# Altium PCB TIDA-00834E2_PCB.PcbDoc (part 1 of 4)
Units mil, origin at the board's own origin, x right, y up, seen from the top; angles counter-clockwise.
Board outline 7480.31 x 4133.86 mil, 4 copper layers (Top Layer, GND, PWR, Bottom Layer), stack 61.912 mil thick; 550 components, 248 nets, 1167 pads, 312 vias.
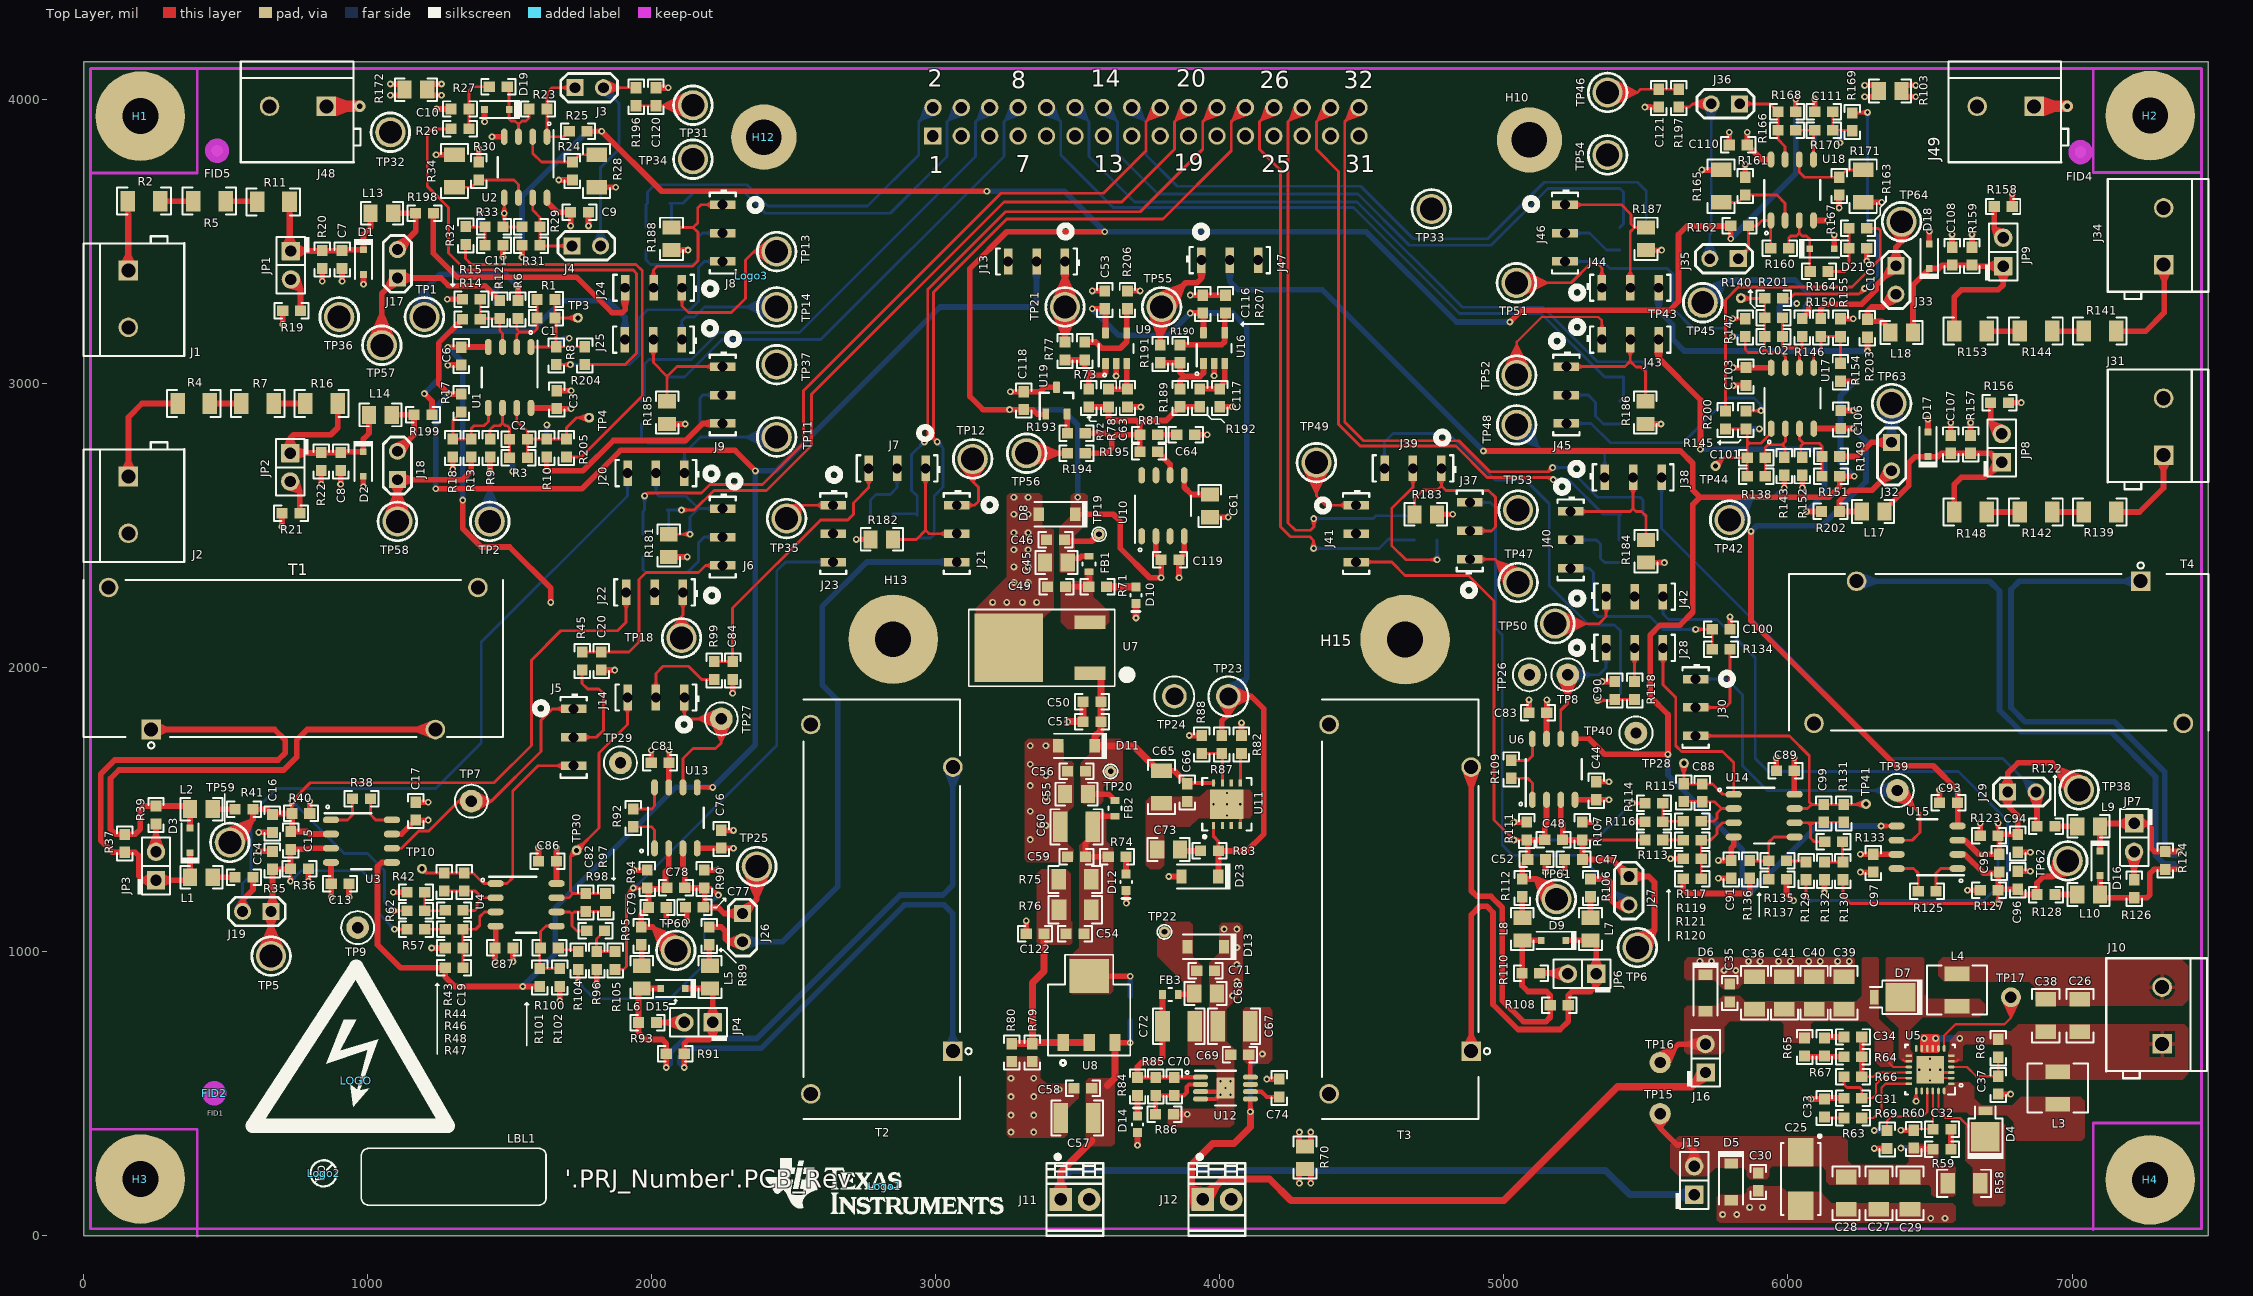
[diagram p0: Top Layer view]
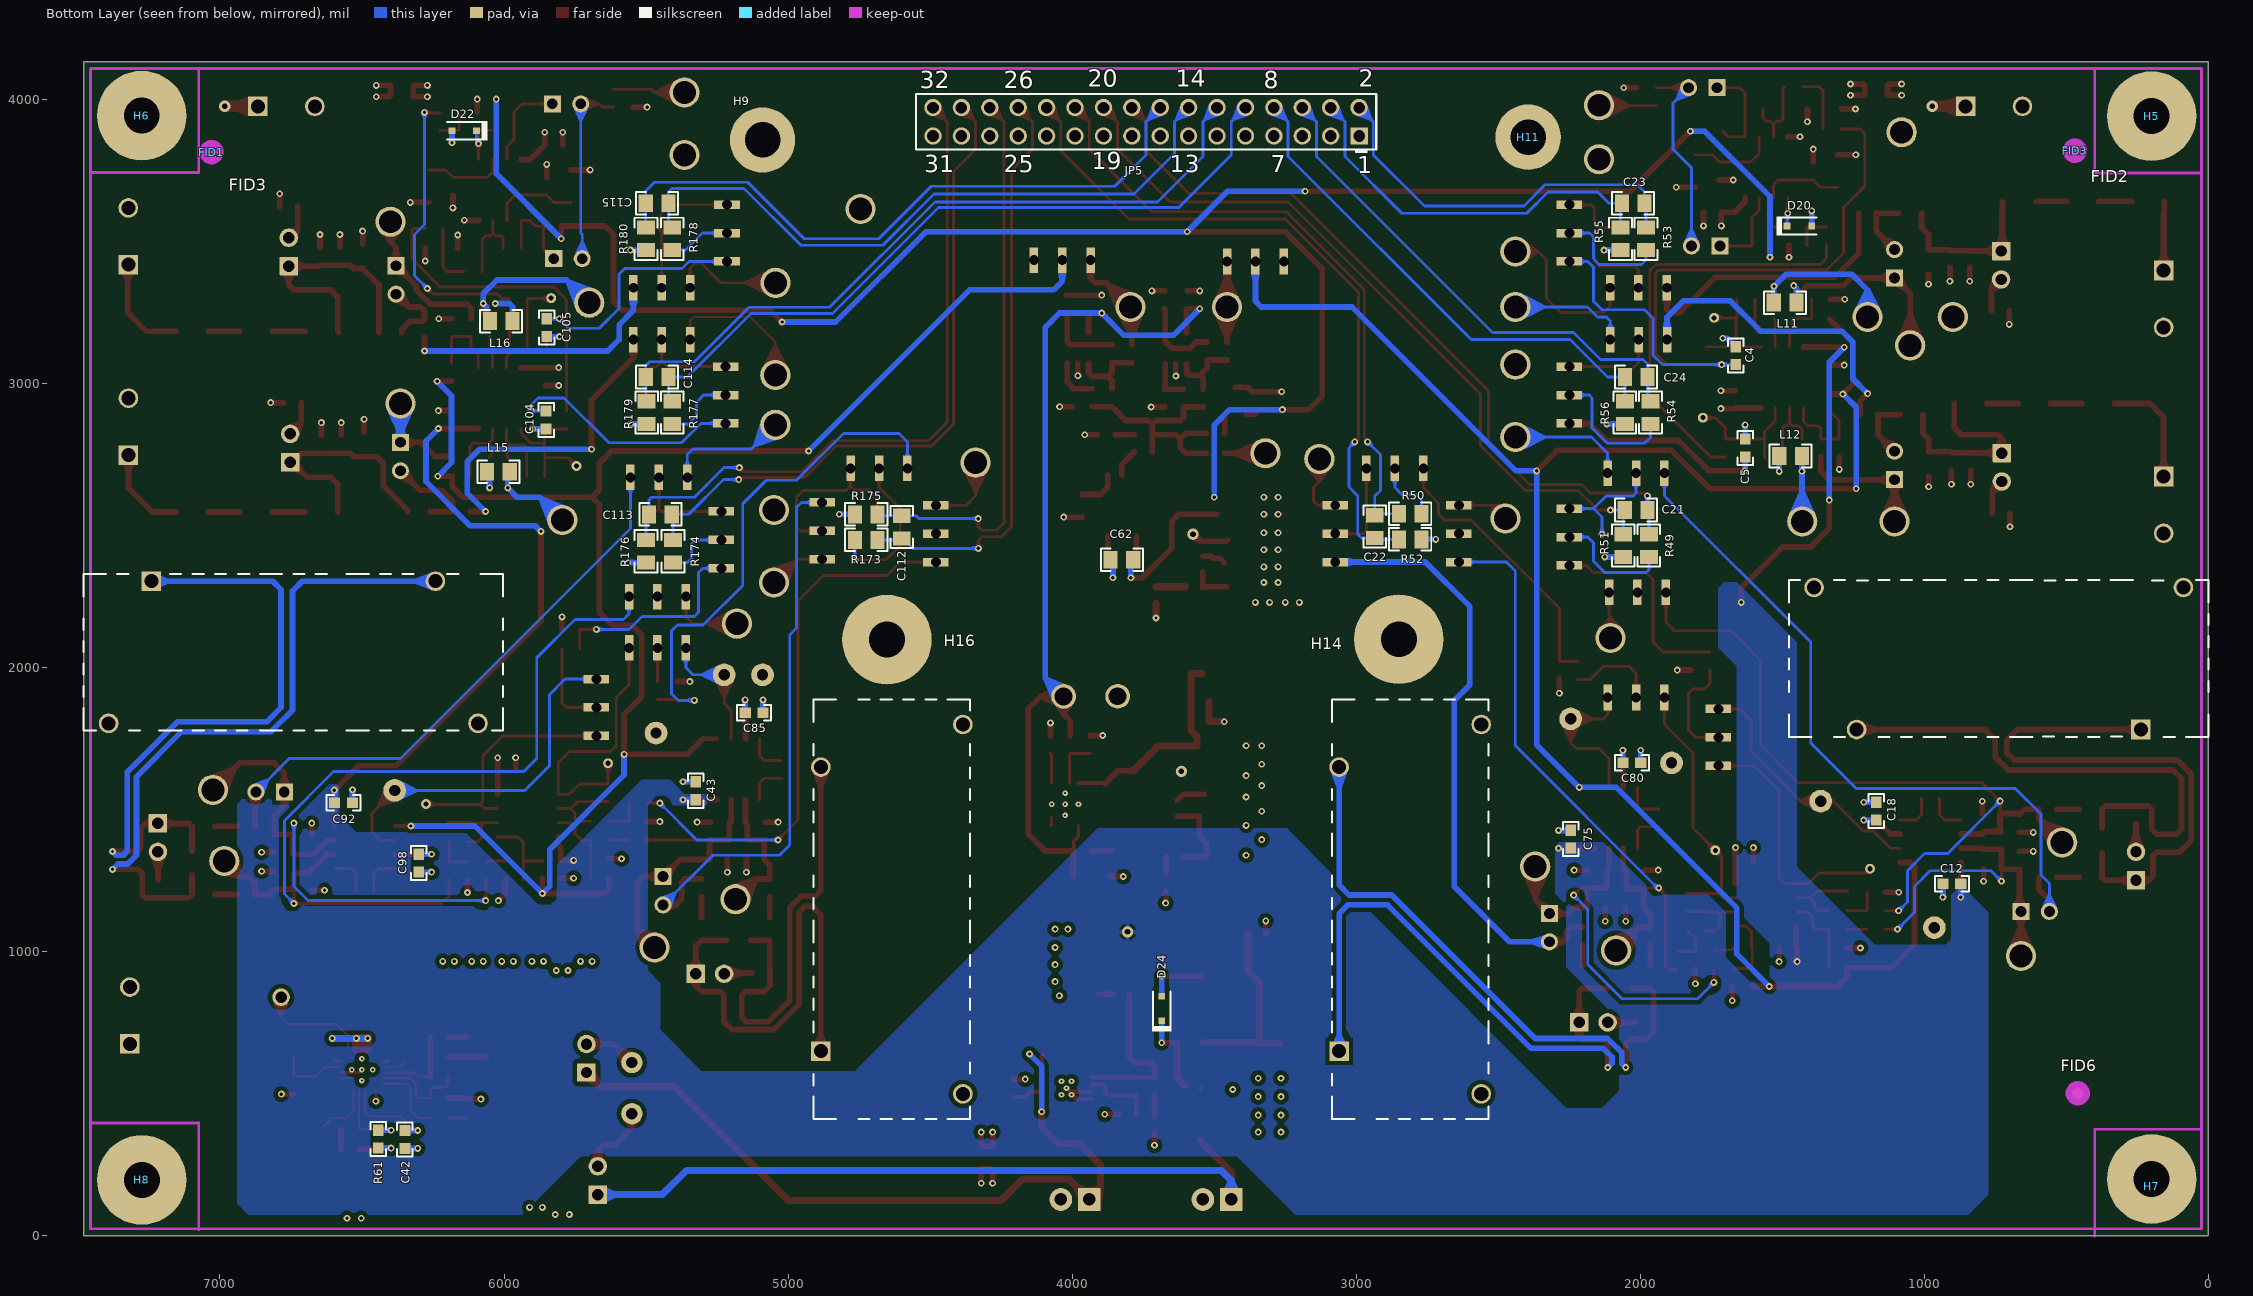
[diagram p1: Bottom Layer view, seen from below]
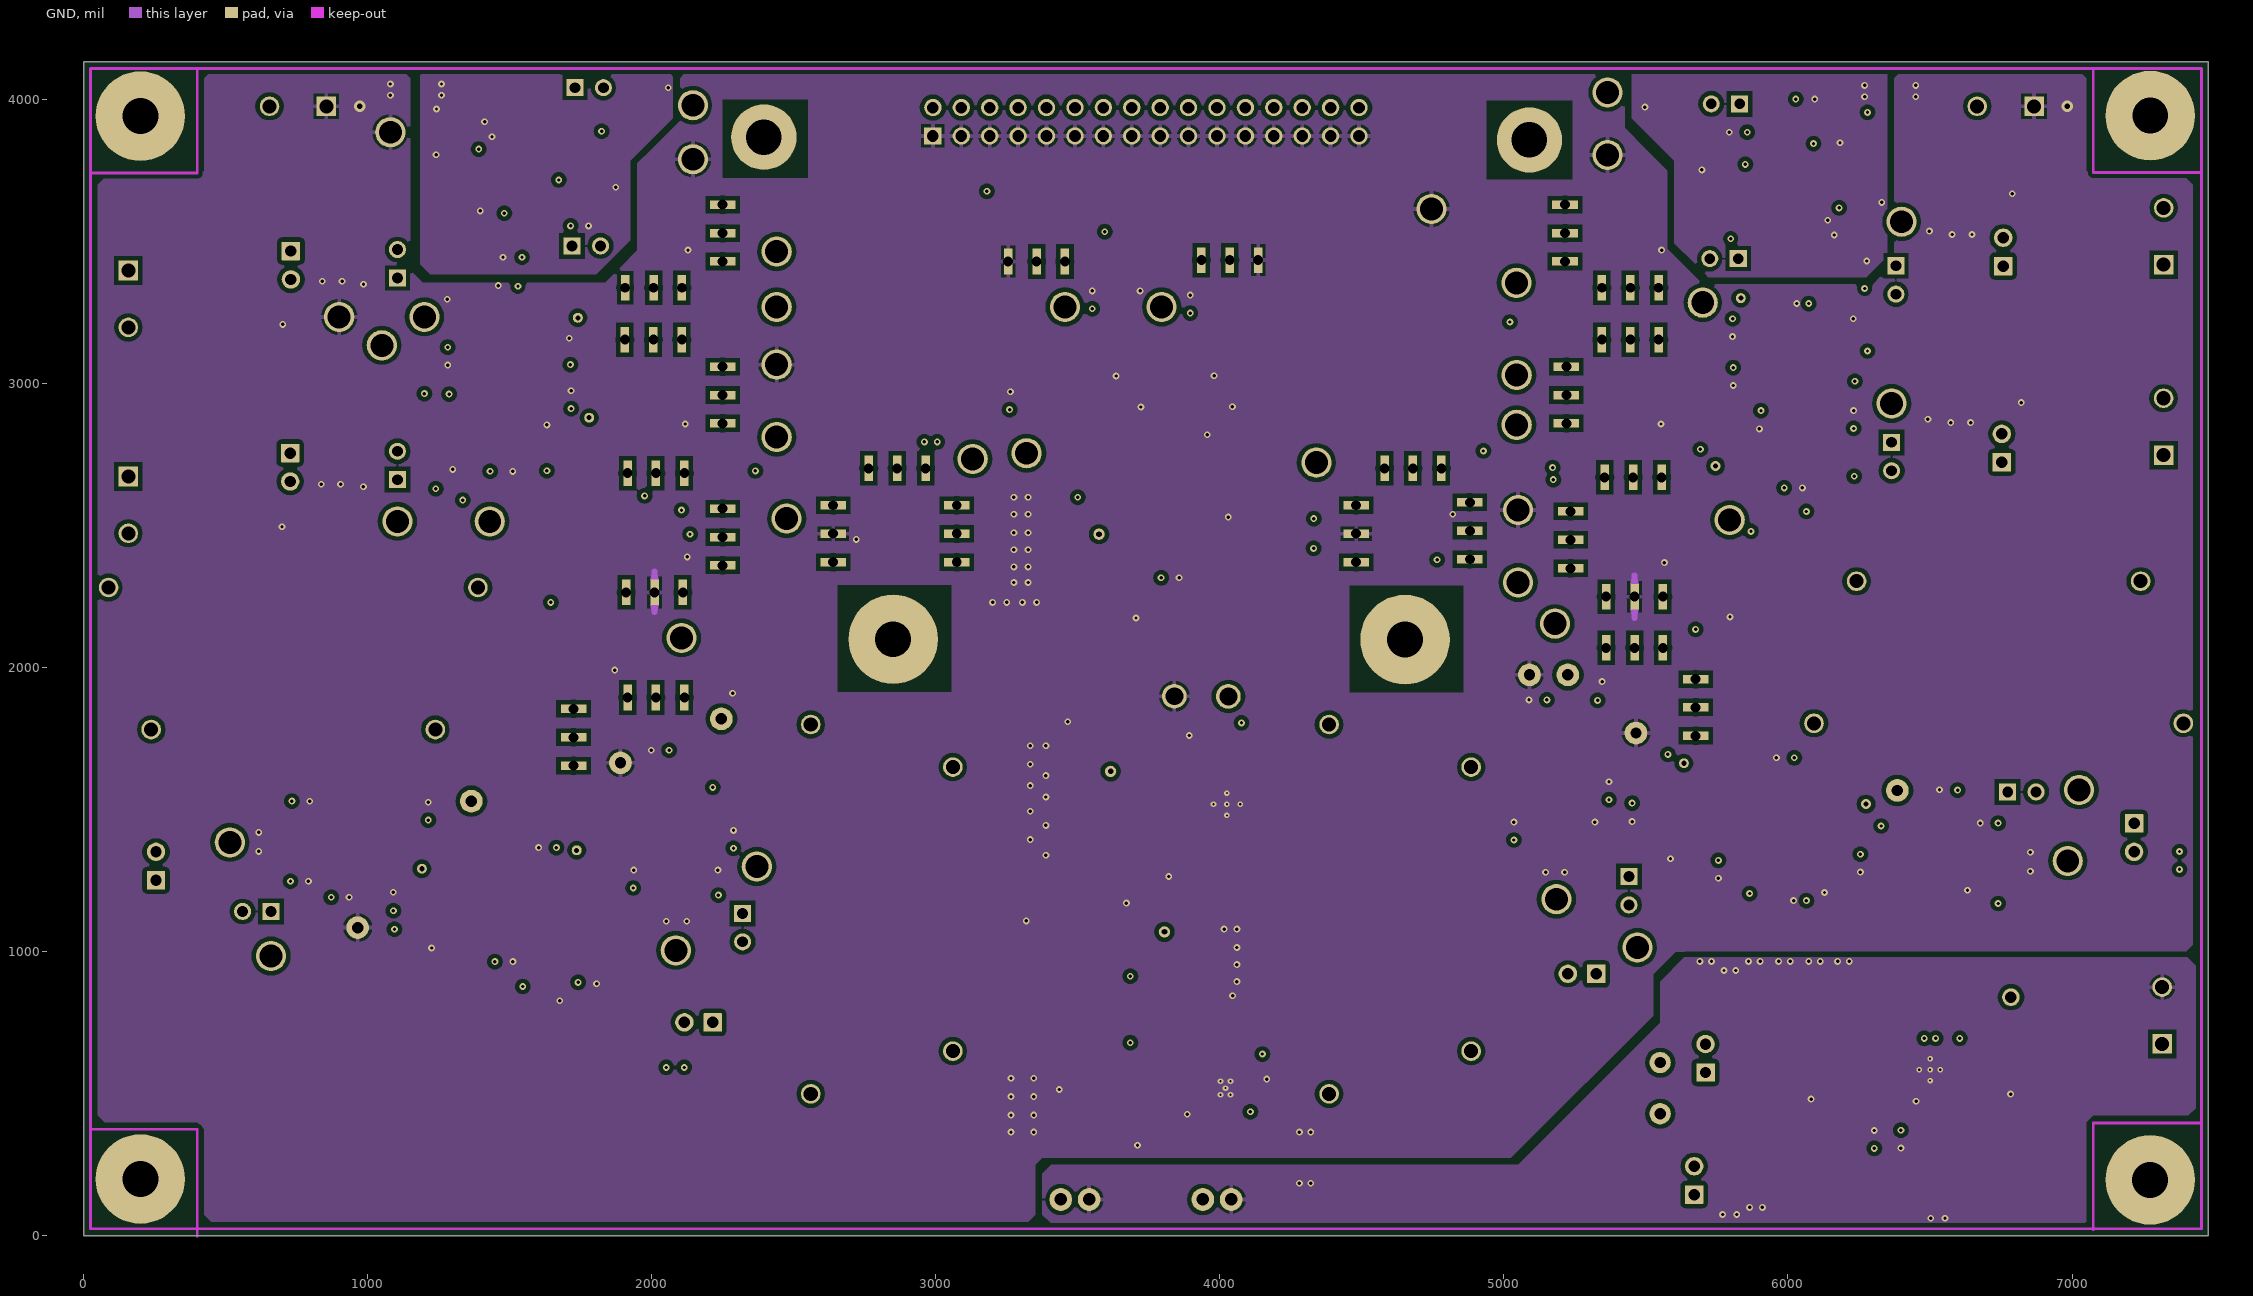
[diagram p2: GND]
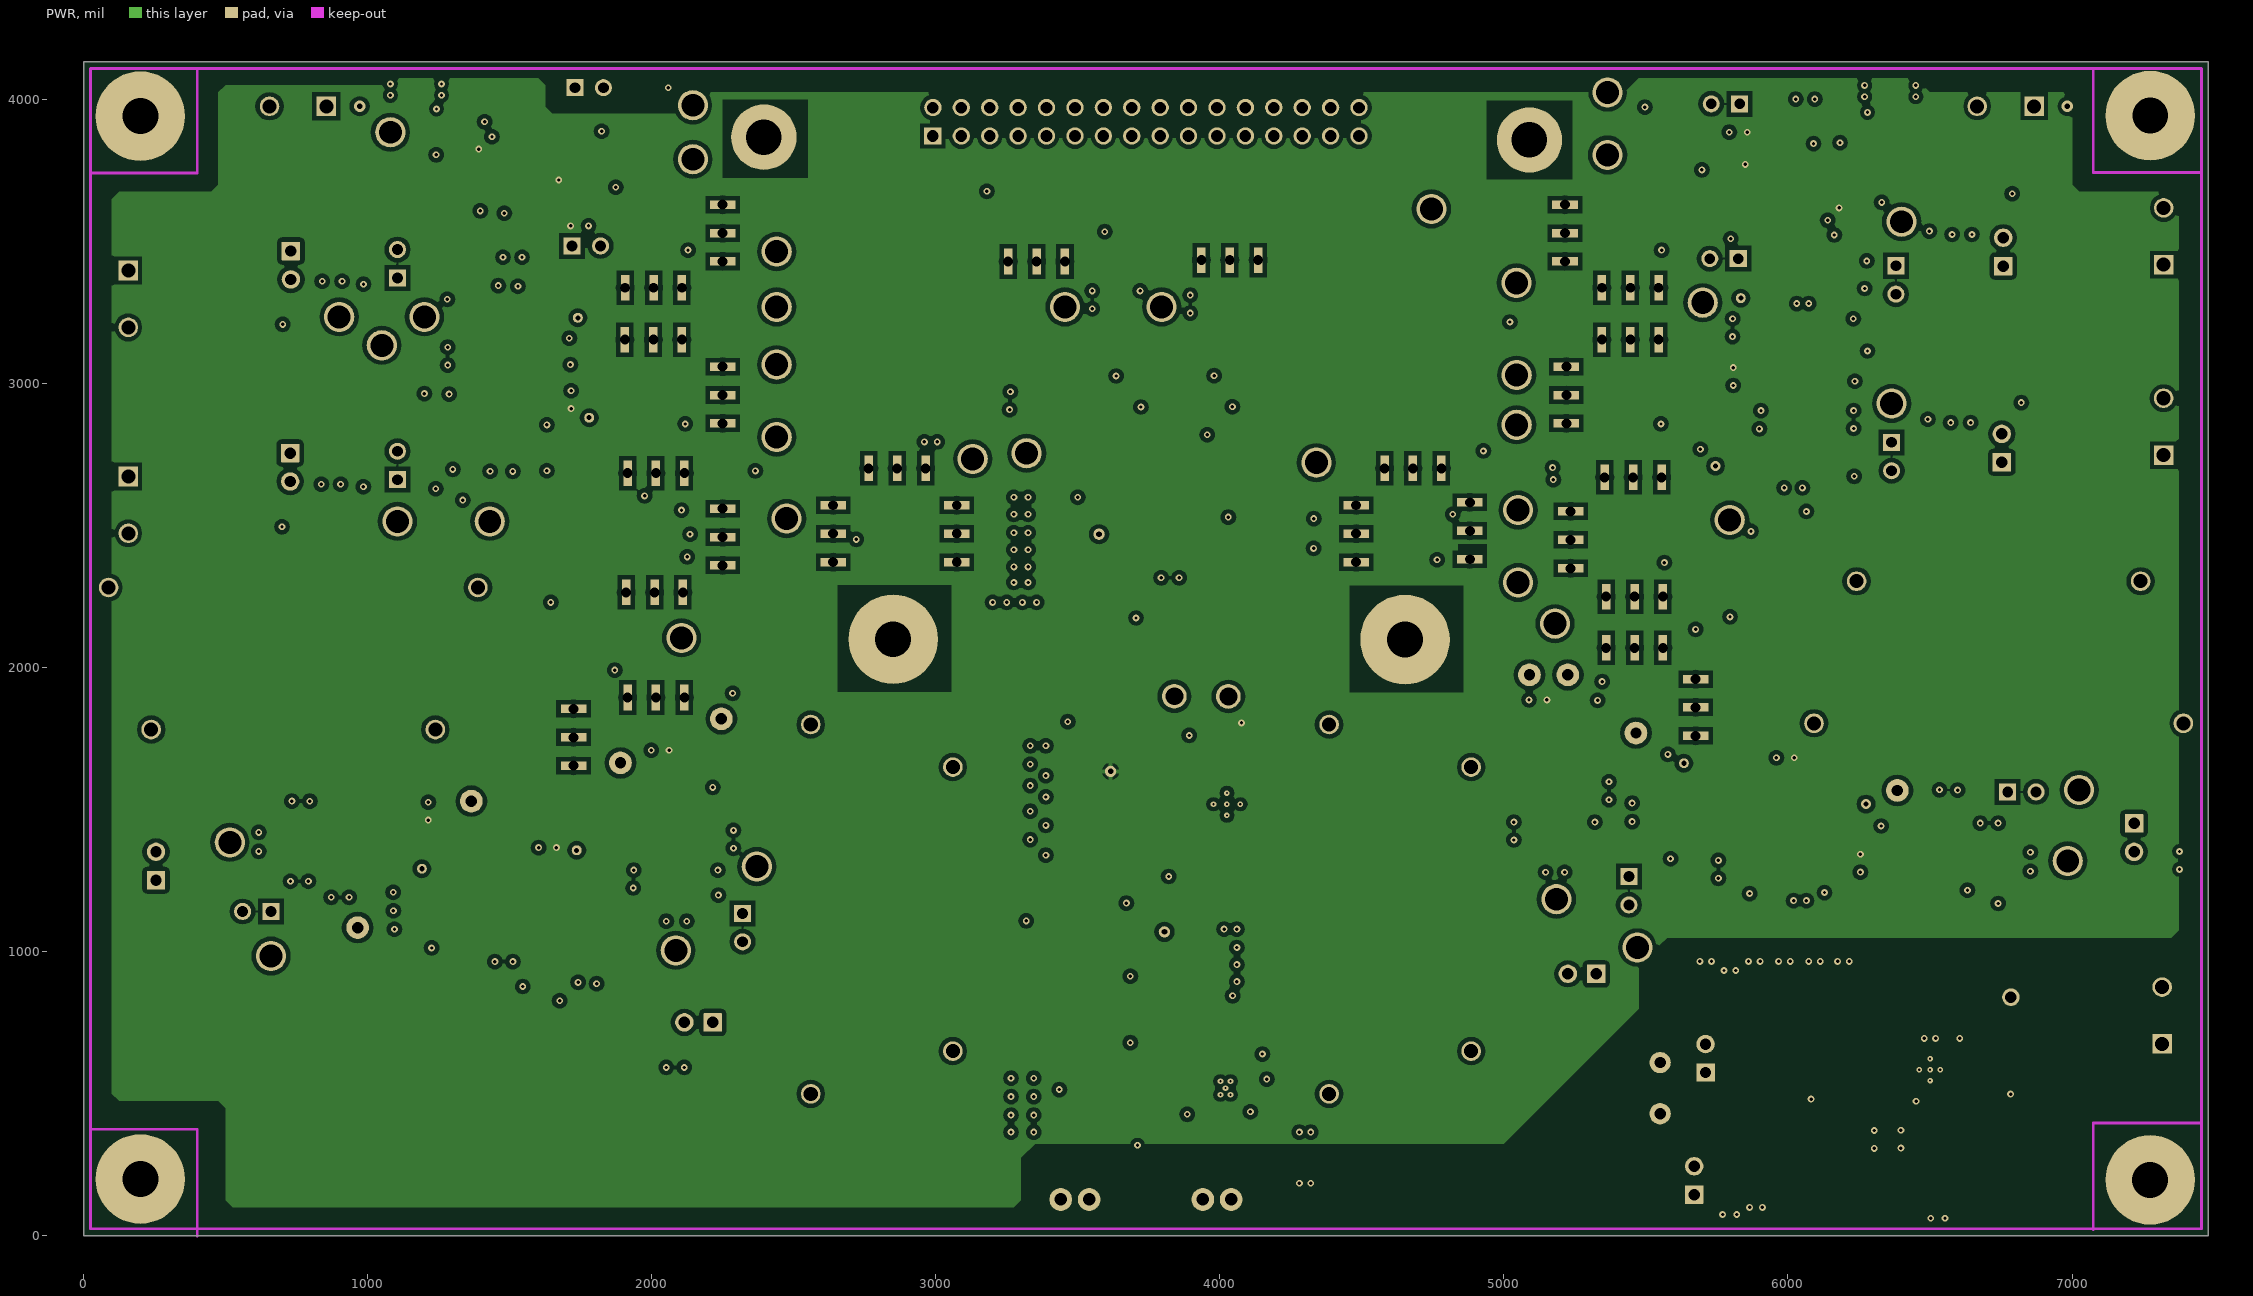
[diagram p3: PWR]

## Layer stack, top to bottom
Top Solder: solder mask 0.4, Solder Resist, Dk 4.3
Top Layer: signal copper 1.378
Dielectric1: prepreg 6.7, FR-4 High Tg, Dk 4.3
GND: signal copper 1.378
Dielectric 2: core 43, FR-4 High Tg, Dk 4.3
PWR: signal copper 1.378
Dielectric 3: prepreg 6.7, FR-4 High Tg, Dk 4.3
Bottom Layer: signal copper 1.378
Bottom Solder: solder mask 0.4, Solder Resist, Dk 4.3

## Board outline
0,0 0,4133.86 7480.31,4133.86 7480.31,0

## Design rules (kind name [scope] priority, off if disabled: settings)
AcuteAngle [All] p1: minimum=4.50000000000000E+0001 checktracksonly=FALSE
AssemblyTestPointUsage [All] p1: valid=2
Clearance Clearance_Keepouts [((IsTrack Or IsArc) And Not InPoly) And IsFree and IsKeepOut vs ((IsTrack Or IsArc) And Not InPoly) And IsFree and IsKeepOut] p1: gap=0
Clearance Clearance_Poly [InPolygon] p2: gap=25 except(8: SMDPad-Poly; 15: Track-Poly THPad-Poly Via-Poly; 20: Poly-Poly)
Clearance [All] p3: gap=7.87
ComponentClearance ComponentClearance_MountingHoles_FiducialMarks [InComponentClass('Mounting Holes') vs InComponentClass('FiducialMark')] p1: gap=50 collisioncheckmode=3 verticalgap=10 showdistances=FALSE
ComponentClearance ComponentClearance_Shunt [InComponentClass('Header') vs InComponentClass('Shunt')] p2: gap=0 collisioncheckmode=3 verticalgap=0 showdistances=FALSE
ComponentClearance ComponentClearance_Logo [InComponentClass('Logo')] p3: gap=50 collisioncheckmode=3 verticalgap=10 showdistances=FALSE
ComponentClearance ComponentClearance_ScrewToNut [(HasFootprint('NY PMS 440 0025 PH')) vs (HasFootprint('Keystone_1902C'))] p4: gap=5 collisioncheckmode=3 verticalgap=10 showdistances=FALSE
ComponentClearance ComponentClearance_MountingHoles [InComponentClass('Mounting Holes')] p5: gap=150 collisioncheckmode=3 verticalgap=100000 showdistances=FALSE
ComponentClearance ComponentClearance_SmallPassives [HasFootprint('0201*') or HasFootprint('0402*') or HasFootprint('0508') or HasFootprint('0603*') or HasFootprint('0612') or HasFootprint('0805*') or HasFootprint('0815*') or HasFootprint('0830*') or HasFootprint('1206*') or HasFootprint('1210*') or HasFootprint('1808*') or HasFootprint('1812*') or HasFootprint('1825*') or HasFootprint('2010*') or HasFootprint('2220*') or HasFootprint('2225*') or HasFootprint('2512*') or HasFootprint('2728*') or HasFootprint('3518*') vs HasFootprint('0201*') or HasFootprint('0402*') or HasFootprint('0508') or HasFootprint('0603*') or HasFootprint('0612') or HasFootprint('0805*') or HasFootprint('0815*') or HasFootprint('0830*') or HasFootprint('1206*') or HasFootprint('1210*') or HasFootprint('1808*') or HasFootprint('1812*') or HasFootprint('1825*') or HasFootprint('2010*') or HasFootprint('2220*') or HasFootprint('2225*') or HasFootprint('2512*') or HasFootprint('2728*') or HasFootprint('3518*')] p6: gap=14.96 collisioncheckmode=3 verticalgap=10 showdistances=FALSE
ComponentClearance ComponentClearance_THtoSMT [IsThruComponent vs IsSMTComponent] p7: gap=40 collisioncheckmode=3 verticalgap=30 showdistances=FALSE
ComponentClearance ComponentClearance_THtoTH [IsThruComponent vs IsThruComponent] p8: gap=30 collisioncheckmode=3 verticalgap=30 showdistances=FALSE
ComponentClearance [All] p9: gap=30 collisioncheckmode=3 verticalgap=10 showdistances=FALSE
DiffPairsRouting [All] p1: maxlimit=100 minlimit=10 mostfreqgap=10 toplayer_minwidth=15 toplayer_maxwidth=15 toplayer_prefwidth=15 midlayer1_minwidth=15 midlayer1_maxwidth=15 midlayer1_prefwidth=15 midlayer2_minwidth=15 midlayer2_maxwidth=15 midlayer2_prefwidth=15 bottomlayer_minwidth=15 bottomlayer_maxwidth=15 bottomlayer_prefwidth=15 maxuncoupledlength=1000
FabricationTestPointUsage TestPointUsage [All] p1: valid=2 allowmultiple=FALSE
FabricationTestpoint Testpoint [All] p1: side=3 testpointundercomponent=TRUE minsize=40 maxsize=100 preferedsize=60 minholesize=0 maxholesize=40 preferedholesize=32 testpointgrid=1 allowsidetop=TRUE allowsidebottom=TRUE usegrid=TRUE gridtolerance=0.01
FanoutControl Fanout_LCC [IsLCC] p1: bgadir=Out bgaviamode=Centered fanoutstyle=Auto fanoutdirection=Alternating viagrid=1 // Fanout_LCC (Default Rule)
FanoutControl Fanout_BGA [IsBGA] p2: bgadir=Out bgaviamode=Centered fanoutstyle=Auto fanoutdirection=Alternating viagrid=1 // Fanout_BGA (Default Rule)
FanoutControl Fanout_Default [All] p4: bgadir=Out bgaviamode=Centered fanoutstyle=Auto fanoutdirection=Alternating viagrid=1 // Fanout_Default (Default Rule)
FanoutControl Fanout_Small [(CompPinCount < 5)] p5: bgadir=Out bgaviamode=Centered fanoutstyle=Auto fanoutdirection=OutThenIn viagrid=1 // Fanout_Small (Default Rule)
HoleSize [All] p1: absolutevalues=TRUE maxlimit=251 minlimit=7.87 maxpercent=80.000 minpercent=20.000
MinimumAnnularRing MinimumAnnularRing_ThermalPadVias [IsVia and InAnyComponent] p1: minimumring=5.91
MinimumAnnularRing [All] p2: minimumring=6
MinimumSolderMaskSliver MinimumSolderMaskSliver_Logo [InComponentClass('Logo') vs InComponentClass('Logo')] p1: minsoldermaskwidth=0.7
MinimumSolderMaskSliver [All] p2: minsoldermaskwidth=3.94
PlaneConnect [All] p1: planeconnectstyle=Relief reliefexpansion=10 reliefentries=4 reliefconductorwidth=10 reliefairgap=10
PolygonConnect PolygonConnect_TH [IsThruPin] p1: connectstyle=Relief reliefconductorwidth=15 reliefentries=4 polygonreliefangle="90 Angle" airgapwidth=10
PolygonConnect [All] p2: connectstyle=Direct reliefconductorwidth=10 reliefentries=4 polygonreliefangle="90 Angle" airgapwidth=10
PolygonConnect PolygonConnect_via [Isvia] p3: connectstyle=Direct reliefconductorwidth=10 reliefentries=4 polygonreliefangle="90 Angle" airgapwidth=10
RoutingVias ThermalPadVias [IsVia and InAnyComponent] p1: holewidth=7.87 width=19.68 viastyle="Through Hole" minholewidth=7.87 minwidth=19.68 maxholewidth=12.99 maxwidth=23.62
RoutingVias [All] p2: holewidth=12 width=24 viastyle="Through Hole" minholewidth=7.87 minwidth=20 maxholewidth=20 maxwidth=40
SilkToSilkClearance SilkToSilkClearance_Pb-FreeLogo [(HasFootprint('Pb-Free_Overlay_Medium') OR HasFootprint('Pb-Free_Overlay_Small')) vs (HasFootprint('Pb-Free_Overlay_Medium') OR HasFootprint('Pb-Free_Overlay_Small'))] p1: silktosilkclearance=0
SilkToSilkClearance [All] p2: silktosilkclearance=0.75
SilkToSolderMaskClearance SilkToComponentPadClearance [IsPad and InAnycomponent] p1: minsilkscreentomaskgap=5 clearancetoexposedcopper=TRUE
SilkToSolderMaskClearance "Silk to Solder Mask Opening" [IsPad] p2: minsilkscreentomaskgap=4 clearancetoexposedcopper=TRUE
SolderMaskExpansion [All] p1: expansion=1.97
Width [All] p1: maxlimit=100 minlimit=6 preferedwidth=10 checkconnectedcopper=TRUE
16 further rules are at their usual default settings.

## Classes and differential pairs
component class TIDA-00834E1_Pg3_CT1_CT2: C12 C13 C14 C15 C16 C17 C18 C19 C20 C75 C76 C77 C78 C79 C80 C81 C82 C84 C86 C87 D3 D15 J5 J14 J19 J26 JP3 JP4 L1 L2 L5 L6 R35 R36 R37 R38 R39 R40 R41 R42 R43 R44 R45 R46 R47 R48 R57 R62 R89 R90 R91 R92 R93 R94 R95 R96 R97 R98 R99 R100 R101 R102 R104 R105 SH-J1 SH-J2 T1 T2 TP5 TP7 TP9 TP10 TP25 TP27 TP29 TP30 TP59 TP60 U3 U4 U13
component class TIDA-00834E1_Pg5_VOLTAGE: C1 C2 C3 C4 C5 C6 C7 C8 C9 C10 C11 C120 D1 D2 D19 D20 J1 J2 J3 J4 J17 J18 J48 JP1 JP2 L11 L12 L13 L14 R1 R2 R3 R4 R5 R6 R7 R8 R9 R10 R11 R12 R13 R14 R15 R16 R17 R18 R19 R20 R21 R22 R23 R24 R25 R26 R27 R28 R29 R30 R31 R32 R33 R34 R172 R196 R198 R199 R204 R205 TP1 TP2 TP3 TP4 TP31 TP57 TP58 U1 U2
component class Header: J5 J6 J7 J8 J9 J13 J14 J15 J16 J20 J21 J22 J23 J24 J25 J28 J30 J37 J38 J39 J40 J41 J42 J43 J44 J45 J46 J47 JP1 JP2 JP3 JP4 JP6 JP7 JP8 JP9
component class "Mounting Holes": H1 H2 H3 H4 H13 H15
component class Logo: Logo1
component class TIDA-00834E1_Pg10_EVM_Hardware: FID1 FID2 FID3 FID4 FID5 FID6 H1 H2 H3 H4 H5 H6 H7 H8 H9 H10 H11 h12 H13 H14 H15 H16 LBL1 LOGO Logo1 Logo2 Logo3 ZZ1 ZZ2 ZZ3 ZZ4
component class FiducialMark: FID1 FID2 FID3 FID4 FID5 FID6
component class AssemblyNote: ZZ1 ZZ2 ZZ3 ZZ4
component class Label: LBL1
component class TIDA-00834E1_Pg9_Filters: C21 C22 C23 C24 C112 C113 C114 C115 J6 J7 J8 J9 J20 J21 J22 J23 J24 J25 J37 J38 J39 J40 J41 J42 J43 J44 J45 J46 JP5 R49 R50 R51 R52 R53 R54 R55 R56 R173 R174 R175 R176 R177 R178 R179 R180 R181 R182 R183 R184 R185 R186 R187 R188 SH-J3 TP11 TP12 TP13 TP14 TP18 TP32 TP33 TP34 TP35 TP36 TP37 TP47 TP48 TP49 TP50 TP51 TP52 TP53 TP54
component class "TIDA-00834E1_Pg7_Split Rail Converter": C25 C26 C27 C28 C29 C30 C31 C32 C33 C34 C35 C36 C37 C38 C39 C40 C41 C42 D4 D5 D6 D7 J10 J11 J12 J15 J16 L3 L4 R58 R59 R60 R61 R63 R64 R65 R66 R67 R68 R69 R70 TP15 TP16 TP17 U5
component class TIDA-00834E1_Pg8_LDO: C45 C46 C49 C50 C51 C53 C54 C55 C56 C57 C58 C59 C60 C61 C62 C63 C64 C65 C66 C67 C68 C69 C70 C71 C72 C73 C74 C116 C117 C118 C119 C122 D8 D10 D11 D12 D13 D14 D23 D24 FB1 FB2 FB3 J13 J47 R71 R72 R73 R74 R75 R76 R77 R78 R79 R80 R81 R82 R83 R84 R85 R86 R87 R88 R189 R190 R191 R192 R193 R194 R195 R206 R207 SH-J4 TP19 TP20 TP21 TP22 TP23 TP24 TP55 TP56 U7 U8 U9 U10 U11 U12 U16 U19
component class TIDA-00834E1_Pg4_CT3_CT4: C43 C44 C47 C48 C52 C83 C85 C88 C89 C90 C91 C92 C93 C94 C95 C96 C97 C98 C99 C100 D9 D16 J27 J28 J29 J30 JP6 JP7 L7 L8 L9 L10 R106 R107 R108 R109 R110 R111 R112 R113 R114 R115 R116 R117 R118 R119 R120 R121 R122 R123 R124 R125 R126 R127 R128 R129 R130 R131 R132 R133 R134 R135 R136 R137 SH-J15 SH-J16 T3 T4 TP6 TP8 TP26 TP28 TP38 TP39 TP40 TP41 TP61 TP62 U6 U14 U15
component class TIDA-00834E1_Pg6_VOLTAGE2: C101 C102 C103 C104 C105 C106 C107 C108 C109 C110 C111 C121 D17 D18 D21 D22 J31 J32 J33 J34 J35 J36 J49 JP8 JP9 L15 L16 L17 L18 R103 R138 R139 R140 R141 R142 R143 R144 R145 R146 R147 R148 R149 R150 R151 R152 R153 R154 R155 R156 R157 R158 R159 R160 R161 R162 R163 R164 R165 R166 R167 R168 R169 R170 R171 R197 R200 R201 R202 R203 SH-J19 SH-J20 SH-J21 TP42 TP43 TP44 TP45 TP46 TP63 TP64 U17 U18

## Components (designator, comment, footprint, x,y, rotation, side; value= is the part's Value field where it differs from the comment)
C1 "06033C101KAT2A" 0603#1 1627.59,3231.23 r0 top
C2 "06033C101KAT2A" 0603#1 1531.12,2804.81 r0 top
C3 "06033C104JAT2A" 0603#1 1666.12,2943.51 r270 top
C4 "06033C101KAT2A" 0603#1 1663.7,3098.51 r90 bottom
C5 "06033C101KAT2A" 0603#1 1631.12,2773.51 r90 bottom
C6 "06033C104JAT2A" 0603#1 1330,3096.85 r90 top
C7 "C1608C0G1H102J" 0603#1 910,3436.85 r90 top
C8 "C1608C0G1H102J" 0603#1 905,2725.55 r90 top
C9 "06033C104JAT2A" 0603#1 1746.12,3603.51 r180 top
C10 "C1608C0G1E103J" 0603#1 1325,3966.85 r0 top
C11 "C1608C0G1E103J" 0603#1 1445,3486.85 r180 top
C12 "GRM188R61C105KA93D" 0603#1 903.19,1239.33 r0 bottom
C13 "CGA3E2X8R1E104K080AA" 0603#1 903.19,1239.33 r0 top
C14 "C0603X102K5RACTU" 0603#1 665,1321.85 r90 top
C15 "06031C103KAT2A" 0603#1 730,1391.85 r90 top
C16 "C0603X102K5RACTU" 0603#1 665,1451.85 r90 top
C17 "CGA3E2X8R1E104K080AA" 0603#1 1170,1494.98 r90 top
C18 "GRM188R61C105KA93D" 0603#1 1170,1494.98 r90 bottom
C19 "06033C101KAT2A" 0603#1 1339.76,1245.52 r90 top
C20 "06033C101KAT2A" 0603#1 1822.09,2023.26 r270 top
C21 "C0805C103K5RACTU" 0805_HV 2015,2555 r0 bottom
C22 "C0805C103K5RACTU" 0805_HV 2935,2496.85 r270 bottom
C23 "C0805C103K5RACTU" 0805_HV 2025,3635 r0 bottom
C24 "C0805C103K5RACTU" 0805_HV 2014.43,3023.05 r0 bottom
C25 "293D475X9025C2TE3" 6032-28 6045,200 r270 top
C26 "C3216X7R1E475M" 1206 7027.52,775 r90 top
C27 "C3216X7R1E475M" 1206 6320,150 r270 top
C28 "C3216X7R1E475M" 1206 6205,150 r270 top
C29 "C3216X7R1E475M" 1206 6430,150 r270 top
C30 "GRM188R70J103KA01D" 0603#1 5895,190 r270 top
C31 "C0603C224K9RACTU" 0603#1 6228.5,485 r0 top
C32 "C0603C100J5GACTU" 0603#1 6542.52,375.47 r180 top
C33 "GRM188R70J103KA01D" 0603#1 6128.5,450 r270 top
C34 "C0603C100J5GACTU" 0603#1 6228.5,700 r0 top
C35 "GRM188R70J103KA01D" 0603#1 5795,855 r90 top
C36 "C3216X7R1E475M" 1206 5882.52,855.47 r90 top
C37 "GRM188R61E105KA12D" 0603#1 6740,530.47 r270 top
C38 "C3216X7R1E475M" 1206 6907.52,775 r90 top
C39 "C3216X7R1E475M" 1206 6197.52,855.47 r90 top
C40 "C3216X7R1E475M" 1206 6092.52,855.47 r90 top
C41 "C3216X7R1E475M" 1206 5987.52,855.47 r90 top
C42 "GRM188R70J103KA01D" 0603#1 6348.82,339.17 r90 bottom
C43 "GRM188R61C105KA93D" 0603#1 5325,1566.85 r90 bottom
C44 "CGA3E2X8R1E104K080AA" 0603#1 5325.07,1566.85 r90 top
C45 "C2012X5R1H475M125AB" 0805_HV 3425,2370 r180 top
C46 "C0603C104K5RACTU" 0603#1 3421.85,2450 r180 top
C47 "C0603X102K5RACTU" 0603#1 5245.32,1325 r180 top
C48 "06031C103KAT2A" 0603#1 5175.32,1395 r180 top
C49 "CGA3E3X5R1H105K080AB" 0603#1 3425,2285 r180 top
C50 "CGA3E3X5R1H105K080AB" 0603#1 3550,1880 r180 top
C51 "C0603C104K5RACTU" 0603#1 3550,1810 r180 top
C52 "C0603X102K5RACTU" 0603#1 5115.32,1325 r180 top
C53 "C0603C104J4RACTU" 0603#1 3595,3295 r270 top
C54 "06031C103KAT2A" 0603#1 3490,1064 r180 top
C55 "C2012X5R1H475M125AB" 0805_HV 3495.53,1555 r180 top
C56 "C0603C104K5RACTU" 0603#1 3495.53,1635 r180 top
C57 "GMK325AB7106MM-T" 1210 3497.91,415 r180 top
C58 "C0603C104K5RACTU" 0603#1 3517.91,520 r180 top
C59 "UMK107ABJ474KA-T" 0603#1 3495.53,1335 r180 top
C60 "GMK325AB7106MM-T" 1210 3495.53,1440 r180 top
C61 "C0805C105K8RACTU" 0805_HV 3965,2570 r270 top
C62 "C0805C105K8RACTU" 0805_HV 3825,2380 r0 bottom
C63 "C0603C104K8RACTU" 0603#1 3675,2949.25 r90 top
C64 "EMK107BBJ106MA-T" 0603#1 3880,2820 r0 top
C65 "885012208069" 1206 3795,1580 r270 top
C66 "06033C104JAT2A" 0603#1 3885,1560 r270 top
C67 "GMK325AB7106MM-T" 1210 4050.31,737.75 r0 top
C68 "C2012X5R1H475M125AB" 0805_HV 3950.31,852.75 r180 top
C69 "C0603C104K5RACTU" 0603#1 4070.31,637.75 r180 top
C70 "06031C103KAT2A" 0603#1 3839.04,525.75 r90 top
C71 "C0603C104K5RACTU" 0603#1 3950.31,932.75 r0 top
C72 "GMK325AB7106MM-T" 1210 3855.31,737.75 r180 top
C73 "C0805C225K8RACTU" 0805_HV 3820,1360 r180 top
C74 "06031C103KAT2A" 0603#1 4209.04,520.26 r270 top
C75 "GRM188R61C105KA93D" 0603#1 2245,1396.45 r90 bottom
C76 "CGA3E2X8R1E104K080AA" 0603#1 2245,1396.45 r90 top
C77 "C0603X102K5RACTU" 0603#1 2150,1156.85 r180 top
C78 "06031C103KAT2A" 0603#1 2085,1225.9 r180 top
C79 "C0603X102K5RACTU" 0603#1 2020,1155.9 r180 top
C80 "CGA3E2X8R1E104K080AA" 0603#1 2030,1665.9 r180 bottom
C81 "GRM188R61C105KA93D" 0603#1 2030,1665.9 r180 top
C82 "06033C101KAT2A" 0603#1 1767.61,1173.4 r90 top
C83 "CGA3E2X8R1E104K080AA" 0603#1 5119.68,1841.78 r180 top
C84 "06033C101KAT2A" 0603#1 2285,1990 r270 top
C85 "GRM188R61C105KA93D" 0603#1 5119.68,1841.72 r180 bottom
C86 "CGA3E2X8R1E104K080AA" 0603#1 1633.26,1318.4 r180 top
C87 "CGA3E2X8R1E104K080AA" 0603#1 1479.76,1013.4 r0 top
C88 "06033C101KAT2A" 0603#1 5698.17,1559.47 r90 top
C89 "CGA3E2X8R1E104K080AA" 0603#1 5990.79,1637.8 r180 top
C90 "06033C101KAT2A" 0603#1 5390,1920 r90 top
C91 "CGA3E2X8R1E104K080AA" 0603#1 5800,1290 r270 top
C92 "GRM188R61C105KA93D" 0603#1 6565,1525 r180 bottom
C93 "CGA3E2X8R1E104K080AA" 0603#1 6565,1525.07 r180 top
C94 "C0603X102K5RACTU" 0603#1 6808.5,1381.81 r270 top
C95 "06031C103KAT2A" 0603#1 6743.51,1311.81 r270 top
C96 "C0603X102K5RACTU" 0603#1 6808.51,1251.81 r270 top
C97 "CGA3E2X8R1E104K080AA" 0603#1 6300,1311.81 r270 top
C98 "GRM188R61C105KA93D" 0603#1 6300.07,1311.81 r270 bottom
C99 "06033C101KAT2A" 0603#1 6126.02,1487.34 r90 top
C100 "06033C101KAT2A" 0603#1 5765,2135 r0 top
C101 "06033C101KAT2A" 0603#1 5888.36,2739.33 r180 top
C102 "06033C101KAT2A" 0603#1 5949.84,3165.74 r180 top
C103 "06033C104JAT2A" 0603#1 5852.26,3025 r90 top
C104 "06033C101KAT2A" 0603#1 5852.26,2872.04 r270 bottom
C105 "06033C101KAT2A" 0603#1 5849.84,3197.04 r270 bottom
C106 "06033C104JAT2A" 0603#1 6185.96,2873.7 r270 top
C107 "C1608C0G1H102J" 0603#1 6572.83,2786.5 r270 top
C108 "C1608C0G1H102J" 0603#1 6577.83,3448.62 r270 top
C109 "C1608C0G1E103J" 0603#1 6246.12,3476.84 r180 top
C110 "06033C104JAT2A" 0603#1 5825,3840.19 r0 top
C111 "C1608C0G1E103J" 0603#1 6126.12,3956.84 r0 top
C112 "C0805C103K5RACTU" 0805_HV 4600,2495 r90 bottom
C113 "C0805C103K5RACTU" 0805_HV 5450,2540.01 r0 bottom
C114 "C0805C103K5RACTU" 0805_HV 5461.06,3023.05 r0 bottom
C115 "C0805C103K5RACTU" 0805_HV 5461.06,3635 r0 bottom
C116 "C0603C104J4RACTU" 0603#1 3940,3280 r270 top
C117 "C0603C104K8RACTU" 0603#1 4000,2950 r90 top
C118 "C0603C104K5RACTU" 0603#1 3310,2940 r90 top
C119 "C0603C104K5RACTU" 0603#1 3825,2380 r0 top
C120 "C1608C0G1E103J" 0603#1 2015,4010 r270 top
C121 "C1608C0G1E103J" 0603#1 5545,4005 r90 top
C122 "C1608X5R1V335K080AC" 0603#1 3350,1064 r180 top
D1 "PESD12VL1BA" SOD-323#1 985.48,3427.57 r270 top
D2 "PESD12VL1BA" SOD-323#1 985,2716.85 r270 top
D3 "PESD12VL1BA" SOD-323#2 375,1392.17 r90 top
D4 "MBRM120ET1G" POWERMITE 6695,395 r90 top
D5 "DZ2W15000L" SOD-123 5800,190 r270 top
D6 "DZ2W15000L" SOD-123 5710,855 r270 top
D7 "MBRM120ET1G" POWERMITE 6350,840 r180 top
D8 "MMSZ4685T1G" SOD-123 3426.85,2540 r180 top
D9 "PESD12VL1BA" SOD-323#2 5175,1040 r180 top
D10 "LG L29K-G2J1-24-Z" "LG L29K_GREEN" 3705,2255 r270 top
D11 "DZ2W15000L" SOD-123 3495.53,1725 r180 top
D12 "LG L29K-G2J1-24-Z" "LG L29K_GREEN" 3670.53,1245 r270 top
D13 "DZ2W15000L" SOD-123 3950.31,1017.75 r180 top
D14 "LG L29K-G2J1-24-Z" "LG L29K_GREEN" 3710.24,392.56 r90 top
D15 "PESD12VL1BA" SOD-323#1 2075,870.9 r180 top
D16 "PESD12VL1BA" SOD-323#2 7098.51,1311.49 r270 top
D17 "PESD12VL1BA" SOD-323#2 6492.83,2786.5 r90 top
D18 "PESD12VL1BA" SOD-323#2 6497.83,3448.62 r90 top
D19 "BAV19WS-7-F" SOD-323#1 1455,3965 r180 top
D20 "BAV19WS-7-F" SOD-323#1 1440,3555 r180 bottom
D21 "BAV19WS-7-F" SOD-323#1 6120,3475 r0 top
D22 "BAV19WS-7-F" SOD-323#1 6140,3890 r0 bottom
D23 "MMSZ5232B-7-F" SOD-123 3930,1265 r180 top
D24 "BAS316,115" sod-323 3685,800 r90 bottom
FB1 "MMZ1608B102CTA00" MMZ1608_095 3540,2365 r90 top
FB2 "MMZ1608B102CTA00" MMZ1608_095 3630.53,1505 r90 top
FB3 "MMZ1608B102CTA00" MMZ1608_095 3825.78,850.13 r0 top
FID1 "Fiducial" Fiducial10-20 7030,3815 r180 bottom
FID2 "Fiducial" Fiducial10-20 460,501.85 r0 top
FID3 "Fiducial" Fiducial10-20 470,3820 r180 bottom
FID4 "Fiducial" Fiducial10-20 7030,3815 r0 top
FID5 "Fiducial" Fiducial10-20 470,3820 r0 top
FID6 "Fiducial" Fiducial10-20 460,501.85 r180 bottom
H1 "NY PMS 440 0025 PH" "NY PMS 440 0025 PH" 200,3941.85 r0 top locked
H2 "NY PMS 440 0025 PH" "NY PMS 440 0025 PH" 7275.53,3943.7 r0 top locked
H3 "NY PMS 440 0025 PH" "NY PMS 440 0025 PH" 200,200 r0 top locked
H4 "NY PMS 440 0025 PH" "NY PMS 440 0025 PH" 7275,196.85 r0 top locked
H5 "1902C" Keystone_1902C#1 200,3941.85 r180 bottom locked
H6 "1902C" Keystone_1902C#1 7275.53,3943.7 r180 bottom locked
H7 "1902C" Keystone_1902C#1 200,175 r180 bottom locked
H8 "1902C" Keystone_1902C#1 7275,196.85 r180 bottom locked
H9 "PMSSS 440 0025 PH" B_F_PMSSS4400025PH#1 -250,7868.85 r180 bottom
H10 "1891" Keystone_1891 5090,3857.85 r0 top
H11 "PMSSS 440 0025 PH" B_F_PMSSS4400025PH#2 2395,3867.85 r180 bottom (schematic designator H1)
H12 "1891" Keystone_1891 2395,3867.85 r0 top (schematic designator H5)
H13 "NY PMS 440 0025 PH" "NY PMS 440 0025 PH" 2850,2100 r0 top
H14 "1902C" Keystone_1902C#2 2908,2066 r180 bottom
H15 "NY PMS 440 0025 PH" "NY PMS 440 0025 PH" 4652,2099 r0 top
H16 "1902C" Keystone_1902C#2 4650,2100 r180 bottom
J1 "ED120/2DS" CONN_ED120-2DS 157.48,3298.23 r180 top
J2 "ED120/2DS" CONN_ED120-2DS 157.48,2573.23 r180 top
J3 "JUMPER_2X100MIL" HDR100_1X2 1730,4041.85 r0 top
J4 "JUMPER_2X100MIL" HDR100_1X2 1720,3485 r0 top
J5 "5-146280-3" TE_5-146280-3 1725,1755 r270 top
J6 "5-146280-3" TE_5-146280-3 2250,2460 r270 top
J7 "5-146280-3" TE_5-146280-3 2864,2701.85 r180 top
J8 "5-146280-3" TE_5-146280-3 2250,3530 r270 top
J9 "5-146280-3" TE_5-146280-3 2250,2960 r270 top
J10 "ED120/2DS" CONN_ED120-2DS 7317.52,775.47 r0 top
J11 "CON-OSTVN02A150" CN2_MTB_P100_PD80_D1.1_S5.54X6.5_STACK 3490,127.95 r0 top
J12 "CON-OSTVN02A150" CN2_MTB_P100_PD80_D1.1_S5.54X6.5_STACK 3990,127.95 r0 top
J13 "5-146280-3" TE_5-146280-3 3355,3430 r180 top
J14 "5-146280-3" TE_5-146280-3 2015,1895 r180 top
J15 "5-146280-2" TSW-102-07-G-S 5670,195 r90 top
J16 "5-146280-2" TSW-102-07-G-S 5710,625 r90 top
J17 "JUMPER_2X100MIL" HDR100_1X2 1105,3371.85 r90 top
J18 "JUMPER_2X100MIL" HDR100_1X2 1105,2661.85 r90 top
J19 "JUMPER_2X100MIL" HDR100_1X2 660,1141.85 r180 top
J20 "5-146280-3" TE_5-146280-3 2015,2685 r180 top
J21 "5-146280-3" TE_5-146280-3 3074,2471.85 r270 top
J22 "5-146280-3" TE_5-146280-3 2010,2265 r180 top
J23 "5-146280-3" TE_5-146280-3 2639,2471.85 r270 top
J24 "5-146280-3" TE_5-146280-3 2006.57,3337.64 r180 top
J25 "5-146280-3" TE_5-146280-3 2006.01,3155 r180 top
J26 "JUMPER_2X100MIL" HDR100_1X2 2320,1135 r270 top
J27 "JUMPER_2X100MIL" HDR100_1X2 5440,1265 r270 top
J28 "5-146280-3" TE_5-146280-3 5460,2070 r0 top
J29 "JUMPER_2X100MIL" HDR100_1X2 6773.5,1562.8 r0 top
J30 "5-146280-3" TE_5-146280-3 5675,1860 r270 top
J31 "ED120/2DS" CONN_ED120-2DS 7322.52,2848.62 r0 top
J32 "JUMPER_2X100MIL" HDR100_1X2 6365,2793.35 r270 top
J33 "JUMPER_2X100MIL" HDR100_1X2 6380,3415 r270 top
J34 "ED120/2DS" CONN_ED120-2DS 7322.83,3518.62 r0 top
J35 "JUMPER_2X100MIL" HDR100_1X2 5825,3440 r180 top
J36 "JUMPER_2X100MIL" HDR100_1X2 5830,3985 r180 top
J37 "5-146280-3" TE_5-146280-3 4880,2481.85 r90 top
J38 "5-146280-3" TE_5-146280-3 5455,2670.01 r0 top
J39 "5-146280-3" TE_5-146280-3 4680,2701.85 r180 top
J40 "5-146280-3" TE_5-146280-3 5235,2450.01 r270 top
J41 "5-146280-3" TE_5-146280-3 4480,2471.85 r270 top
J42 "5-146280-3" TE_5-146280-3 5460,2250 r0 top
J43 "5-146280-3" TE_5-146280-3 5445,3154.99 r0 top
J44 "5-146280-3" TE_5-146280-3 5445,3337.62 r0 top
J45 "5-146280-3" TE_5-146280-3 5220,2960 r270 top
J46 "5-146280-3" TE_5-146280-3 5215,3530 r270 top
J47 "5-146280-3" TE_5-146280-3 4035,3435 r0 top
J48 "ED120/2DS" CONN_ED120-2DS 754.72,3976.38 r90 top
J49 "ED120/2DS" CONN_ED120-2DS 6766.38,3976.38 r90 top
JP1 "5-146280-2" TSW-102-07-G-S 730,3416.85 r270 top
JP2 "5-146280-2" TSW-102-07-G-S 727.48,2705.59 r270 top
JP3 "5-146280-2" TSW-102-07-G-S 255,1301.85 r90 top
JP4 "5-146280-2" TSW-102-07-G-S 2165,751.45 r180 top
JP5 "5-534206-8" Samtec_SSW-116-01-x-D 3740,3921.85 r0 bottom
JP6 "5-146280-2" TSW-102-07-G-S 5275.32,922.4 r180 top
JP7 "5-146280-2" TSW-102-07-G-S 7218.51,1401.81 r270 top
JP8 "5-146280-2" TSW-102-07-G-S 6752.83,2773.15 r90 top
JP9 "5-146280-2" TSW-102-07-G-S 6757.83,3463.62 r90 top
L1 "FBMJ2125HM210NT" 0805_HV 415,1262.17 r0 top
L2 "FBMJ2125HM210NT" 0805_HV 415,1502.17 r0 top
L3 "VLF504012MT-4R7M" IND_VLF504012 6950,520 r270 top
L4 "VLF504012MT-4R7M" IND_VLF504012 6595,865 r90 top
L5 "FBMJ2125HM210NT" 0805_HV 2205,910.9 r90 top
L6 "FBMJ2125HM210NT" 0805_HV 1965,910.9 r90 top
L7 "FBMJ2125HM210NT" 0805_HV 5305,1080 r90 top
L8 "FBMJ2125HM210NT" 0805_HV 5065,1080 r90 top
L9 "FBMJ2125HM210NT" 0805_HV 7058.5,1441.5 r180 top
L10 "FBMJ2125HM210NT" 0805_HV 7058.5,1201.49 r180 top
L11 "FBMJ2125HM210NT" 0805_HV 1490,3285 r0 bottom
L12 "FBMJ2125HM210NT" 0805_HV 1471.14,2745 r180 bottom
L13 "FBMJ2125HM210NT" 0805_HV 1050,3600 r0 top
L14 "FBMJ2125HM210NT" 0805_HV 1045,2890 r0 top
L15 "FBMJ2125HM210NT" 0805_HV 6020,2690 r180 bottom
L16 "FBMJ2125HM210NT" 0805_HV 6010,3220 r0 bottom
L17 "FBMJ2125HM210NT" 0805_HV 6300,2550 r180 top
L18 "FBMJ2125HM210NT" 0805_HV 6400,3180 r180 top
LBL1 "Size: 0.65\" x 0.20 \"" Label_650x200 1303,208 r0 top
LOGO "DANGER HIGH VOLTAGE" IEC_HighVoltage_Large 960,546.32 r0 top (schematic designator LOGO?)
Logo1 "Texas Instruments" TI_Stacked_Overlay_Small 2820,175 r0 top
Logo2 "Pb-Free Symbol" Pb-Free_Overlay_Small 845,220 r90 top
Logo3 "FCC disclaimer" FCC_disclaimer 2350,3380 r0 top
R1 "CRCW060356K2FKEA" 0603#1 1627.59,3296.23 r180 top
R2 "RC1206FR-07330KL" 1206 212.91,3642.36 r180 top
R3 "CRCW060356K2FKEA" 0603#1 1531.12,2738.51 r180 top
R4 "RC1206FR-07330KL" 1206 387.91,2930 r180 top
R5 "RC1206FR-07330KL" 1206 442.91,3642.36 r180 top
R6 "CRCW060310K0FKEA" 0603#2 894.25,2056.22 r90 top
R7 "RC1206FR-07330KL" 1206 612.91,2930 r180 top
R8 "CRCW0603100RFKEA" 0603#1 1663.7,3098.51 r270 top
R9 "CRCW060310K0FKEA" 0603#1 1431.12,2773.19 r270 top
R10 "CRCW0603100RFKEA" 0603#1 1631.12,2773.51 r270 top
R11 "RC1206FR-07330KL" 1206 667.91,3640 r180 top
R12 "CRCW060310K0FKEA" 0603#2 830,2056.22 r90 top
R13 "CRCW060310K0FKEA" 0603#1 1365,2773.19 r270 top
R14 "RC0603FR-0768KL" 0603#1 1365,3226.85 r0 top
R15 "RC0603FR-0768KL" 0603#1 1365,3296.85 r0 top
R16 "RC1206FR-07330KL" 1206 837.91,2930 r180 top
R17 "RC0603FR-0768KL" 0603#1 1330,2931.85 r270 top
R18 "RC0603FR-0768KL" 0603#1 1300,2773.19 r90 top
R19 "CRCW06033K90FKEA" 0603#1 732.52,3256.85 r0 top
R20 "RC0603FR-0730KL" 0603#1 840,3436.85 r90 top
R21 "CRCW06033K90FKEA" 0603#1 730,2544.21 r0 top
R22 "RC0603FR-0730KL" 0603#1 837,2725.55 r90 top
R23 "CRCW06031M00FKEA" 0603#1 1600,3966.85 r180 top
R24 "CRCW060310K0FKEA" 0603#1 1721.12,3748.51 r270 top
R25 "CRCW060310K0FKEA" 0603#1 1741.12,3888.51 r0 top
R26 "CRCW0603100RFKEA" 0603#1 1325,3896.85 r0 top
R27 "CRCW060310K0FKEA" 0603#1 1460,4045 r0 top
R28 "CRCW12061K00FKEA" 1206 1806.12,3748.51 r90 top
R29 "CRCW06031M00FKEA" 0603#1 1575,3551.85 r180 top
R30 "CRCW060310K0FKEA" 0603#1 1391.12,3748.51 r90 top
R31 "CRCW060310K0FKEA" 0603#1 1575,3486.85 r180 top
R32 "CRCW0603100RFKEA" 0603#1 1345,3521.85 r90 top
R33 "CRCW060310K0FKEA" 0603#1 1445,3551.85 r0 top
R34 "CRCW12061K00FKEA" 1206 1306.12,3748.51 r270 top
R35 "RT0603BRD07249RL" 0603#1 565,1262.17 r0 top
R36 "RC0603FR-07100KL" 0603#1 760,1291.85 r180 top
R37 "RC0603FR-07169RL" 0603#1 145,1381.85 r270 top
R38 "RG1608P-562-B-T5" 0603#1 978.19,1539.33 r0 top
R39 "CRCW060315R0FKEA" 0603#1 255,1481.85 r270 top
R40 "RC0603FR-07100KL" 0603#1 765,1486.85 r0 top
R41 "RT0603BRD07249RL" 0603#1 565,1502.17 r0 top
R42 "RC0603JR-070RL" 0603#1 1169.68,1209.4 r0 top
R43 "RG1608P-823-B-T5" 0603#1 1269.76,1245.52 r270 top
R44 "RC0603FR-078K2L" 0603#1 1304.76,1145.52 r180 top
R45 "CRCW0603100RFKEA" 0603#1 1755,2023.26 r90 top
R46 "RC0603FR-078K2L" 0603#1 1304.68,1079.4 r180 top
R47 "RC0603FR-07100KL" 0603#1 1304.76,943.4 r0 top
R48 "RC0603FR-07100KL" 0603#1 1304.76,1013.4 r0 top
R49 "CRCW08051K00FKEA" 0805_HV 1970,2430 r90 bottom
R50 "CRCW08051K00FKEA" 0805_HV 2810,2541.85 r0 bottom
R51 "CRCW08051K00FKEA" 0805_HV 2060,2430 r90 bottom
R52 "CRCW08051K00FKEA" 0805_HV 2810,2451.85 r0 bottom
R53 "CRCW08051K00FKEA" 0805_HV 1980,3510 r90 bottom
R54 "CRCW08051K00FKEA" 0805_HV 1964.43,2898.05 r90 bottom
R55 "CRCW08051K00FKEA" 0805_HV 2070,3510 r90 bottom
R56 "CRCW08051K00FKEA" 0805_HV 2054.43,2898.05 r90 bottom
R57 "RC0603JR-070RL" 0603#1 1169.68,1079.4 r180 top
R58 "CRCW12060000Z0EA" 1206 6620,185 r180 top
R59 "CRCW06030000Z0EA" 0603#1 6542.52,305.47 r180 top
R60 "CRCW0603576KFKEA" 0603#1 6442.52,340.47 r270 top
R61 "RG1608P-4992-B-T5" 0603#1 6442.52,340.47 r270 bottom
R62 "RC0603JR-070RL" 0603#1 1169.68,1144.4 r180 top
R63 "CRCW06030000Z0EA" 0603#1 6228.5,415 r180 top
R64 "CRCW0603620KFKEA" 0603#1 6228.5,630 r180 top
R65 "CRCW06030000Z0EA" 0603#1 6058.5,665 r90 top
R66 "RG1608P-4992-B-T5" 0603#1 6228.5,560 r0 top
R67 "RG1608P-4992-B-T5" 0603#1 6128.5,665 r270 top
R68 "CR0603-J/-1R0ELF" 0603#1 6740,660.47 r270 top
R69 "CRCW06031K00JNEA" 0603#1 6348.82,339.17 r270 top
R70 "CRCW08050000Z0EA" 0805_HV 4300,275 r270 top
R71 "CRCW0603300RJNEA" 0603#1 3570,2285 r180 top
R72 "CRCW06030000Z0EA" 0603#1 3538.15,2949.25 r270 top
R73 "CRCW06030000Z0EA" 0603#1 3525,3115 r90 top
R74 "CRCW06033K90JNEA" 0603#1 3638.52,1335 r180 top
R75 "CRCW12062K00FKEA" 1206 3490.53,1255 r0 top
R76 "CRCW12062K00FKEA" 1206 3491,1148 r0 top
R77 "CRCW06030000Z0EA" 0603#1 3455,3115 r270 top
R78 "CRCW06030000Z0EA" 0603#1 3608.15,2949.25 r270 top
R79 "CRCW06038K45FKEA" 0603#1 3340,645 r90 top
R80 "CRCW0603100KFKEA" 0603#1 3267.91,645 r90 top
R81 "CRCW06030000Z0EA" 0603#1 3750,2820 r0 top
R82 "CRCW060310K0FKEA" 0603#1 4076.3,1730 r90 top
R83 "CRCW06030000Z0EA" 0603#1 3963.7,1355 r0 top
R84 "CRCW06033K90JNEA" 0603#1 3710.31,525.75 r90 top
R85 "CRCW06031M07FKEA" 0603#1 3774.04,525.75 r90 top
R86 "RC0603FR-07100KL" 0603#1 3805.31,427.75 r180 top
R87 "CRCW060331K6FKEA" 0603#1 4006.3,1730 r90 top
R88 "CRCW060310K0FKEA" 0603#1 3936.3,1730 r270 top
R89 "RT0603BRD07249RL" 0603#1 2202.94,1055.9 r90 top
R90 "RC0603FR-07100KL" 0603#1 2185,1255.9 r270 top
R91 "RC0603FR-07169RL" 0603#1 2082.94,640.9 r0 top
R92 "RG1608P-562-B-T5" 0603#1 1935,1471.45 r90 top
R93 "CRCW060315R0FKEA" 0603#1 1985,750.9 r0 top
R94 "RC0603FR-07100KL" 0603#1 1985,1255.9 r90 top
R95 "RT0603BRD07249RL" 0603#1 1962.94,1055.9 r90 top
R96 "RC0603JR-070RL" 0603#1 1806.08,969.17 r270 top
R97 "RG1608P-823-B-T5" 0603#1 1837.61,1173.4 r270 top
R98 "RC0603FR-078K2L" 0603#1 1802.61,1073.4 r0 top
R99 "CRCW0603100RFKEA" 0603#1 2220,1990 r90 top
R100 "RC0603FR-078K2L" 0603#1 1639.76,1013.4 r0 top
R101 "RC0603FR-07100KL" 0603#1 1606.08,909.22 r90 top
R102 "RC0603FR-07100KL" 0603#1 1676.08,909.22 r90 top
R103 "CRCW08050000Z0EA" 0805_HV 6360,4030 r180 top
R104 "RC0603JR-070RL" 0603#1 1741.08,969.22 r270 top
R105 "RC0603JR-070RL" 0603#1 1871.08,969.17 r270 top
R106 "RT0603BRD07249RL" 0603#1 5305,1225 r90 top
R107 "RC0603FR-07100KL" 0603#1 5275.32,1425 r270 top
R108 "RC0603FR-07169RL" 0603#3 5195,836.85 r0 top
R109 "RG1608P-562-B-T5" 0603#1 5025.32,1642.4 r90 top
R110 "CRCW060315R0FKEA" 0603#1 5095,925 r0 top
R111 "RC0603FR-07100KL" 0603#1 5080.32,1425 r90 top
R112 "RT0603BRD07249RL" 0603#1 5065,1225 r90 top
R113 "RC0603JR-070RL" 0603#1 5528.09,1393.34 r180 top
R114 "RC0603JR-070RL" 0603#1 5528.09,1523.34 r180 top
R115 "RG1608P-823-B-T5" 0603#1 5633.7,1560 r270 top
R116 "RC0603JR-070RL" 0603#1 5528.09,1458.34 r0 top
R117 "RC0603FR-078K2L" 0603#1 5663.17,1459.46 r180 top
R118 "CRCW0603100RFKEA" 0603#1 5460,1920 r270 top
R119 "RC0603FR-078K2L" 0603#1 5663.09,1392.8 r180 top
R120 "RC0603FR-07100KL" 0603#1 5663.17,1257.34 r0 top
R121 "RC0603FR-07100KL" 0603#1 5663.17,1327.34 r0 top
R122 "RT0603BRD07249RL" 0603#1 6908.5,1441.5 r180 top
R123 "RC0603FR-07100KL" 0603#1 6708.5,1407.8 r0 top
R124 "RC0603FR-07169RL" 0603#1 7328.5,1321.5 r90 top
R125 "RG1608P-562-B-T5" 0603#1 6490,1212.8 r180 top
R126 "CRCW060315R0FKEA" 0603#1 7218.51,1221.81 r90 top
R127 "RC0603FR-07100KL" 0603#1 6708.5,1216.81 r180 top
R128 "RT0603BRD07249RL" 0603#1 6908.5,1201.5 r180 top
R129 "RC0603JR-070RL" 0603#1 6063.7,1285 r270 top
R130 "RC0603JR-070RL" 0603#1 6193.7,1285 r270 top
R131 "RG1608P-823-B-T5" 0603#1 6196.02,1487.34 r270 top
R132 "RC0603JR-070RL" 0603#1 6128.7,1285 r270 top
R133 "RC0603FR-078K2L" 0603#1 6161.02,1387.34 r0 top
R134 "CRCW0603100RFKEA" 0603#1 5765,2065 r180 top
R135 "RC0603FR-078K2L" 0603#1 5963.7,1320 r0 top
R136 "RC0603FR-07100KL" 0603#1 5865,1290 r90 top
R137 "RC0603FR-07100KL" 0603#1 5963.7,1255 r180 top
R138 "CRCW060356K2FKEA" 0603#1 5888.36,2674.33 r0 top
R139 "RC1206FR-07330KL" 1206 7097.91,2547.83 r0 top
R140 "CRCW060356K2FKEA" 0603#1 5949.84,3232.04 r0 top
R141 "RC1206FR-07330KL" 1206 7097.91,3185 r0 top
R142 "RC1206FR-07330KL" 1206 6872.91,2547.83 r0 top
R143 "CRCW060310K0FKEA" 0603#1 5986.71,2709.33 r270 top
R144 "RC1206FR-07330KL" 1206 6872.91,3185 r0 top
R145 "CRCW0603100RFKEA" 0603#1 5852.26,2872.04 r90 top
R146 "CRCW060310K0FKEA" 0603#1 6049.84,3197.36 r90 top
R147 "CRCW0603100RFKEA" 0603#1 5849.84,3197.04 r90 top
R148 "RC1206FR-07330KL" 1206 6642.91,2547.83 r0 top
R149 "CRCW060310K0FKEA" 0603#1 6150.96,2743.7 r0 top
R150 "CRCW060310K0FKEA" 0603#1 6115.96,3197.36 r90 top
R151 "RC0603FR-0768KL" 0603#1 6150.96,2673.7 r180 top
R152 "RC0603FR-0768KL" 0603#1 6050.96,2709.33 r90 top
R153 "RC1206FR-07330KL" 1206 6642.91,3185 r0 top
R154 "RC0603FR-0768KL" 0603#1 6185,3040 r90 top
R155 "RC0603FR-0768KL" 0603#1 6185,3196.85 r270 top
R156 "CRCW06033K90FKEA" 0603#1 6745,2933.15 r180 top
R157 "RC0603FR-0730KL" 0603#1 6642.83,2786.5 r270 top
R158 "CRCW06033K90FKEA" 0603#1 6757.83,3623.62 r180 top
R159 "RC0603FR-0730KL" 0603#1 6647.83,3448.62 r270 top
R160 "CRCW06031M00FKEA" 0603#1 5971.12,3476.84 r0 top
R161 "CRCW060310K0FKEA" 0603#1 5850,3695.19 r90 top
R162 "CRCW060310K0FKEA" 0603#1 5830,3555.19 r180 top
R163 "CRCW0603100RFKEA" 0603#1 6246.12,3546.68 r180 top
R164 "CRCW060310K0FKEA" 0603#1 6110,3395 r180 top
R165 "CRCW12061K00FKEA" 1206 5765,3695.19 r270 top
R166 "CRCW06031M00FKEA" 0603#1 5996.12,3891.84 r0 top
R167 "CRCW060310K0FKEA" 0603#1 6180,3695.19 r270 top
R168 "CRCW060310K0FKEA" 0603#1 5996.12,3956.68 r0 top
R169 "CRCW0603100RFKEA" 0603#1 6226.12,3921.68 r270 top
R170 "CRCW060310K0FKEA" 0603#1 6126.12,3891.84 r180 top
R171 "CRCW12061K00FKEA" 1206 6265,3695.19 r90 top
R172 "CRCW08050000Z0EA" 0805_HV 1170,4035 r0 top
R173 "CRCW08051K00FKEA" 0805_HV 4725,2450 r180 bottom
R174 "CRCW08051K00FKEA" 0805_HV 5405,2410.01 r90 bottom
R175 "CRCW08051K00FKEA" 0805_HV 4725,2540 r180 bottom
R176 "CRCW08051K00FKEA" 0805_HV 5500,2410.01 r90 bottom
R177 "CRCW08051K00FKEA" 0805_HV 5408,2898.05 r90 bottom
R178 "CRCW08051K00FKEA" 0805_HV 5408,3510 r90 bottom
R179 "CRCW08051K00FKEA" 0805_HV 5498,2898.05 r90 bottom
R180 "CRCW08051K00FKEA" 0805_HV 5500.38,3510 r90 bottom
R181 "CRCW0805100KFKEA" 0805_HV 2060,2430 r90 top
R182 "CRCW0805100KFKEA" 0805_HV 2810,2451.85 r0 top
R183 "CRCW0805100KFKEA" 0805_HV 4725,2540 r180 top
R184 "CRCW0805100KFKEA" 0805_HV 5500,2410 r90 top
R185 "CRCW0805100KFKEA" 0805_HV 2054.43,2898.05 r90 top
R186 "CRCW0805100KFKEA" 0805_HV 5498,2898.05 r90 top
R187 "CRCW0805100KFKEA" 0805_HV 5500.38,3510 r90 top
R188 "CRCW0805100KFKEA" 0805_HV 2070,3510 r90 top
R189 "CRCW06030000Z0EA" 0603#1 3860,2950 r270 top
R190 "CRCW06030000Z0EA" 0603#1 3860,3105 r90 top
R191 "CRCW06030000Z0EA" 0603#1 3790,3105 r270 top
R192 "CRCW06030000Z0EA" 0603#1 3930,2950 r270 top
R193 "CRCW06030000Z0EA" 0603#1 3495,2825 r0 top
R194 "CRCW06030000Z0EA" 0603#1 3495,2755 r0 top
R195 "CRCW06030000Z0EA" 0603#1 3750,2760 r180 top
R196 "CRCW0603100RFKEA" 0603#1 1945,4010 r270 top
R197 "CRCW0603100RFKEA" 0603#1 5615,4005 r90 top
R198 "RC0603JR-070RL" 0603#1 1200,3600 r180 top
R199 "RC0603JR-070RL" 0603#1 1195,2890 r180 top
R200 "RC0603JR-070RL" 0603#1 5780,2872.04 r270 top
R201 "RC0603JR-070RL" 0603#1 5950,3300 r180 top
R202 "RC0603JR-070RL" 0603#4 6015,2545 r0 top
R203 "RC0603JR-070RL" 0603#1 6280,3195 r90 top
R204 "RC0603JR-070RL" 0603#1 1765,3098.51 r90 top
R205 "RC0603JR-070RL" 0603#1 1700,2773.51 r90 top
R206 "CRCW06030000Z0EA" 0603#1 3675,3295 r90 top
R207 "CRCW06030000Z0EA" 0603#1 4020,3280 r90 top
T1 "CR8350-2500-N" XFMR_CR8350-2500-N 738.19,2032.32 r90 top
T2 "CR8350-2500-N" XFMR_CR8350-2500-N 2810,1150 r180 top
T3 "CR8350-2500-N" XFMR_CR8350-2500-N 4635,1150 r180 top
T4 "CR8350-2500-N" XFMR_CR8350-2500-N 6741.81,2054.41 r270 top
TP1 "Suggest using a net name here" Keystone1573-2#1 1200,3235 r180 top
TP2 "Suggest using a net name here" Keystone1573-2#1 1430,2515 r180 top
TP3 "TP-040_RND" TP_H045P075 1740,3231.85 r90 top
TP4 "TP-040_RND" TP_H045P075 1780,2880 r270 top
TP5 "Suggest using a net name here" Keystone1573-2#1 660,985 r180 top
TP6 "Suggest using a net name here" Keystone1573-2#1 5470,1015 r0 top
TP7 "5002" Keystone5002 1365,1530 r180 top
TP8 "5002" Keystone5002 5225,1975 r0 top
TP9 "5001" Keystone5001 965,1085 r180 top
TP10 "TP-040_RND" TP_H045P075 1191.08,1292.32 r90 top
TP11 "Suggest using a net name here" Keystone1573-2#1 2440,2811.85 r0 top
TP12 "Suggest using a net name here" Keystone1573-2#1 3130,2735 r270 top
TP13 "Suggest using a net name here" Keystone1573-2#1 2440,3465 r0 top
TP14 "Suggest using a net name here" Keystone1573-2#1 2440,3270 r180 top
TP15 "TP-5001-BLACK" TH-40 5550,430 r90 top
TP16 "TP-5001-BLACK" TH-40 5550,610 r90 top
TP17 "TP-040_RND" TP-040_RND 6785,840 r0 top
TP18 "Suggest using a net name here" Keystone1573-2#1 2105,2105 r0 top
TP19 "TP1_PD40_D0.5_S50" TP1_PD40_D0.5_S50 3575,2470 r180 top
TP20 "TP1_PD40_D0.5_S50" TP1_PD40_D0.5_S50 3615.53,1635 r90 top
TP21 "Suggest using a net name here" Keystone1573-2#1 3455,3270 r90 top
TP22 "TP1_PD40_D0.5_S50" TP1_PD40_D0.5_S50 3805,1070 r0 top
TP23 "+5V" Keystone5010 4030,1898.87 r270 top
TP24 "" Keystone5126 3840,1899.37 r270 top
TP25 "Suggest using a net name here" Keystone1573-2#1 2370,1300 r90 top
TP26 "5001" Keystone5001 5090,1975 r0 top
TP27 "5002" Keystone5002 2245,1820 r270 top
TP28 "TP-040_RND" TP_H045P075 5633.7,1663.7 r90 top
TP29 "5001" Keystone5001 1890,1665 r270 top
TP30 "TP-040_RND" TP_H045P075 1736.08,1357.32 r270 top
TP31 "Suggest using a net name here" Keystone1573-2#1 2145,3980 r180 top
TP32 "Suggest using a net name here" Keystone1573-2#1 1080,3885 r90 top
TP33 "Suggest using a net name here" Keystone1573-2#1 4745,3615 r90 top
TP34 "Suggest using a net name here" Keystone1573-2#1 2145,3790 r90 top
TP35 "Suggest using a net name here" Keystone1573-2#1 2475,2525 r0 top
TP36 "Suggest using a net name here" Keystone1573-2#2 730,2710 r0 top
TP37 "Suggest using a net name here" Keystone1573-2#1 2440,3066.85 r0 top
TP38 "Suggest using a net name here" Keystone1573-2#1 7025,1570 r0 top
TP39 "5002" Keystone5002 6385,1567.8 r0 top
TP40 "5001" Keystone5001 5465,1770 r0 top
TP41 "TP-040_RND" TP_H045P075 6275,1520 r90 top
TP42 "Suggest using a net name here" Keystone1573-2#1 5795,2520 r180 top
TP43 "Suggest using a net name here" Keystone1573-2#1 5700,3285 r180 top
TP44 "TP-040_RND" TP_H045P075 5745,2710 r90 top
TP45 "TP-040_RND" TP_H045P075 5834,3301 r90 top
TP46 "Suggest using a net name here" Keystone1573-2#1 5365,4025 r0 top
TP47 "Suggest using a net name here" Keystone1573-2#1 5050,2300 r0 top
TP48 "Suggest using a net name here" Keystone1573-2#1 5045,2855 r90 top
TP49 "Suggest using a net name here" Keystone1573-2#1 4340,2721.85 r0 top
TP50 "Suggest using a net name here" Keystone1573-2#1 5180,2155 r90 top
TP51 "Suggest using a net name here" Keystone1573-2#1 5044,3355 r270 top
TP52 "Suggest using a net name here" Keystone1573-2#1 5045,3030 r270 top
TP53 "Suggest using a net name here" Keystone1573-2#1 5050,2555 r90 top
TP54 "Suggest using a net name here" Keystone1573-2#1 5365,3805 r90 top
TP55 "Suggest using a net name here" Keystone1573-2#1 3795,3270 r90 top
TP56 "Suggest using a net name here" Keystone1573-2#1 3320,2755 r0 top
TP57 "Suggest using a net name here" Keystone1573-2#1 1050,3135 r0 top
TP58 "Suggest using a net name here" Keystone1573-2#1 1105,2515 r0 top
TP59 "Suggest using a net name here" Keystone1573-2#1 515,1385 r0 top
TP60 "Suggest using a net name here" Keystone1573-2#1 2085,1005 r0 top
TP61 "Suggest using a net name here" Keystone1573-2#1 5185,1185 r0 top
TP62 "Suggest using a net name here" Keystone1573-2#1 6985,1320 r0 top
TP63 "Suggest using a net name here" Keystone1573-2#1 6365,2930 r0 top
TP64 "Suggest using a net name here" Keystone1573-2#1 6400,3570 r0 top
U1 "OPA2188AID" D0008A_N 1500,3021.85 r270 top
U2 "LM2903DR" D0008A_N 1556.12,3761.85 r270 top
U3 "INA188ID" D0008A_N 978.19,1389.33 r0 top
U4 "OPA2188AID" D0008A_N 1557.95,1165.34 r0 top
U5 "TPS65131RGET" RGE0024B 6500.47,584.8 r180 top
U6 "INA188ID" D0008A_N 5175.31,1642.4 r90 top
U7 "TPS7A6533QKVURQ1" KVU_1 3400,2070 r90 top
U8 "TLV1117-XXCDCY" DCY 3540,782.2 r0 top
U9 "OPA322AIDBVR" DBV0005A_N 3635,3124.69 r90 top
U10 "REF5025AID" D0008A_N 3800,2570 r90 top
U11 "LP2951CSD" SDC08A 4025,1519.37 r90 top
U12 "TPS7A3001DGNR" DGN0008D_N 4020,520.26 r0 top
U13 "INA188ID" D0008A_N 2085,1471.45 r90 top
U14 "OPA2188AID" D0008A_N 5916.37,1479.29 r0 top
U15 "INA188ID" D0008A_N 6490,1367.8 r180 top
U16 "OPA322AIDBVR" DBV0005A_N 3980,3125 r90 top
U17 "OPA2188AID" D0008A_N 6015.96,2948.7 r90 top
U18 "LM2903DR" D0008A_N 6015,3681.85 r90 top
U19 "REF3025AIDBZR" DBZ0003A_N 3425,2940 r90 top
ZZ1 "This Assembly Note is for PCB labels only" AssemblyNoteLabel 171,4685 r0 top
ZZ2 "These assemblies are ESD sensitive, ESD precautions shall be observed." AssemblyNote 170,4582 r0 top
ZZ3 "These assemblies must be clean and free from flux and all contaminants. Use of no clean flux is not acceptable." AssemblyNote 169,4483.56 r0 top
ZZ4 "These assemblies must comply with workmanship standards IPC-A-610 Class 2, unless otherwise specified." AssemblyNote 169,4395 r0 top

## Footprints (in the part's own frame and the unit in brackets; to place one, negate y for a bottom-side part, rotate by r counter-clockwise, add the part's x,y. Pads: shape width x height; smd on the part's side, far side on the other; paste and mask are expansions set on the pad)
0603#1 [mm] "0603 from SM-752 data"
  rect 1x0.95 smd: 1(-0.8,0) 2(0.8,0)
  silkscreen extent -1.52,-0.69 1.52,0.69, body extent -0.87,-0.47 0.87,0.47, height 1
0603#2 [mm] "0603 from SM-752 data"
  rect 1x0.95 smd: 1(29.807,-16.129) 2(31.407,-16.129)
  silkscreen extent 29.08,-16.82 32.13,-15.44, body extent 29.73,-16.6 31.48,-15.65, height 1
0603#3 [mm] "0603 from SM-752 data"
  rect 1x0.95 smd: 1(-0.8,-0.635) 2(0.8,-0.635)
  silkscreen extent -1.52,-1.33 1.52,0.06, body extent -0.87,-1.11 0.87,-0.16, height 1
0603#4 [mm] "0603 from SM-752 data"
  rect 1x0.95 smd: 1(2.629,0.127) 2(4.229,0.127)
  silkscreen extent 1.91,-0.56 4.95,0.82, body extent 2.55,-0.35 4.3,0.6, height 1
0805_HV [mil] "0805 with 30mil clearance between pads"
  rect 50x63 smd: 1(-40,0) 2(40,0)
  silkscreen extent -74,-40 74,40, body extent -43,-29 43,29, height 57
1206 [mm] "1206 from SM-752 data"
  rect 1.3x1.85 smd: 1(-1.45,0) 2(1.45,0)
  silkscreen extent -2.4,-1.21 2.4,1.21, body extent -1.7,-0.9 1.7,0.9, height 1.35
1210 [mm] "1210 from SM-752 data"
  rect 1.3x2.7 smd: 1(-1.45,0) 2(1.45,0)
  silkscreen extent -2.32,-1.57 2.32,1.57, body extent -1.7,-1.35 1.7,1.35, height 1.35
6032-28 [mm] "Medium Density IPC based on Vishay Sprague 293D datasheet."
  rect 2.55x2.3 smd: 1(-2.375,0) 2(2.375,0)
  silkscreen extent -3.96,-1.75 3.2,1.83, body extent -3.15,-1.75 3.15,1.75, height 2.8
AssemblyNote [mil] "Assembly Note"
AssemblyNoteLabel [mil] "Assembly Note for PCB Labels"
B_F_PMSSS4400025PH#1 [mil] "MACHINE SCREW PAN PHILLIPS 4-40"
  round 230 hole 125: 1(-5340,-4011)
  body extent -5450,-4120 -5231,-3901, height 79
B_F_PMSSS4400025PH#2 [mil] "MACHINE SCREW PAN PHILLIPS 4-40"
  round 230 hole 125: 1(0,0)
  body extent -109,-109 110,110, height 79
CN2_MTB_P100_PD80_D1.1_S5.54X6.5_STACK [mil]
  rect 80x80 / inner round 80 / far side rect 80x80 hole 44: 1(-50,0)
  round 80 hole 44: 2(50,0)
  silkscreen extent -100,-128 100,160
CONN_ED120-2DS [mm] "ONSHORE"
  rect 1.75x1.75 hole 1.254: 1(0,-2.54)
  round 1.75 hole 1.254: 2(0,2.54)
  silkscreen extent -5,-5.6 4,5.12, body extent -5,-5.6 4.15,5.12, height 13.1
D0008A_N [mm] "SOIC, 8-Leads, Body 4.9x3.9mm, Pitch 1.27mm, IPC Medium Density"
  oval 1.45x0.6 smd: 1(-2.725,1.905) 2(-2.725,0.635) 3(-2.725,-0.635) 4(-2.725,-1.905) 5(2.725,-1.905) 6(2.725,-0.635) 7(2.725,0.635) 8(2.725,1.905)
  silkscreen extent -3.3,-2.5 0.9,2.5, body extent -3,-2.45 3,2.45, height 1.63
DBV0005A_N [mm] "SOT23, 5-Leads, Body 2.9x1.6mm, Pitch 0.95mm, Lead Span 2.8mm, IPC Medium Density"
  rrect17% 1x0.6 smd: 1(-1.375,0.95) 2(-1.375,0) 3(-1.375,-0.95) 4(1.375,-0.95) 5(1.375,0.95)
  silkscreen extent -1.63,-1.55 0.38,1.55, body extent -1.42,-1.46 1.42,1.46, height 1.09
DBZ0003A_N [mm] "SOT23, 3-Leads, Body 2.9x1.3mm, Pitch 0.95mm, Lead Span 2.4mm, IPC Medium Density"
  rrect17% 1x0.6 smd: 1(-1.2,0.95) 2(-1.2,-0.95) 3(1.2,0)
  silkscreen extent -1.65,-1.5 0.7,1.5, body extent -1.26,-1.46 1.26,1.46, height 0.98
DCY [mil]
  rect 40x60 smd: 1(-91,-102.2) 2(0,-102.2) 3(91,-102.2)
  rect 140x120 smd: 4(0,132.3)
DGN0008D_N [mm] "TSOP, 8-Leads, Body 3x3mm, Pitch 0.65mm, Thermal Pad 1.89x1.57mm, IPC Medium Density"
  rrect100% 1.35x0.45 smd: 1(-2.225,0.975) 2(-2.225,0.325) 3(-2.225,-0.325) 4(-2.225,-0.975) 5(2.225,-0.975) 6(2.225,-0.325) 7(2.225,0.325) 8(2.225,0.975)
  rrect6% 1.57x1.89 smd: 9(0,0)
  silkscreen extent -2.73,-1.55 0.95,1.55, body extent -2.46,-1.5 2.46,1.5, height 1.1
FCC_disclaimer [mil]
Fiducial10-20 [mm]
  round 1 smd mask+0.5: 1(0,0)
  Top Layer keep-out circle w1.178: c0,0 r0.5
HDR100_1X2 [mil]
  rect 60x60 hole 38: 1(0,0)
  round 60 hole 38: 2(100,0)
  silkscreen extent -50,-50 150,50
IEC_HighVoltage_Large [mil]
  silkscreen extent -365,-159 323,401
IND_VLF504012 [mm] "TDK"
  rect 1.3x2.2 smd: 1(-1.45,0) 2(1.45,0)
  silkscreen extent -2.2,-2.7 2.2,2.7, body extent -2.15,-2.65 2.15,2.65, height 1.2
Keystone1573-2#1 [mm] "Double Turret"
  round 2.7 hole 2.05: 1(0,0)
  silkscreen extent -1.73,-1.73 1.73,1.73, body extent -1.18,-1.18 1.17,1.18, height 4.72
Keystone1573-2#2 [mm] "Double Turret"
  round 2.7 hole 2.05: 1(4.318,13.335)
  silkscreen extent 2.59,11.61 6.05,15.06, body extent 3.14,12.16 5.49,14.51, height 4.72
Keystone5001 [mil] "For Keystone 500x miniature loop terminals"
  round 80 hole 40: 1(0,0)
  silkscreen extent -58,-58 58,58, body extent -49,-49 49,49, height 182
Keystone5002 [mil] "For Keystone 500x miniature loop terminals"
  round 80 hole 40: 1(0,0)
  silkscreen extent -58,-58 58,58, body extent -49,-49 49,49, height 182
Keystone5010 [mil] "Keystone Multipurpose loops"
  round 87 hole 63: 1(0,0)
  silkscreen extent -70,-70 70,70, body extent -63,-63 63,62, height 319
Keystone5126 [mil] "Keystone Multipurpose loops"
  round 87 hole 63: 1(0,0)
  silkscreen extent -70,-70 70,70, body extent -63,-63 63,62, height 319
Keystone_1891 [mil] "3/16 Hex Female Standoff"
  body extent -108,-93 108,94, height 245
Keystone_1902C#1 [mil] "Hex Standoff, 4-40 threaded, nylon"
  body extent -145,-126 146,126, height 501
Keystone_1902C#2 [mil] "Hex Standoff, 4-40 threaded, nylon"
  round 1 on Mech4: 0(0,0)
  body extent -145,-126 146,126, height 501
KVU_1 [mm]
  rect 1.2x2.8 smd: 1(-2.29,-3.635) 3(2.29,-3.635)
  rect 6.096x6.096 smd: 2(0,3.635)
  silkscreen extent -3.43,-7.24 3.43,7.22
Label_650x200 [mil] "Thermal Transfer Label"
  silkscreen extent -325,-100 325,100, body extent -325,-100 325,100, height 1
"LG L29K_GREEN" [mm] "OSRAM"
  rect 0.8x0.8 smd: 1(-0.75,0) 2(0.75,0)
  silkscreen extent -0.1,-0.5 1.45,0.5, body extent -0.9,-0.45 0.9,0.45, height 0.67
MMZ1608_095 [mm] "TDK"
  rect 0.6x0.8 smd: 1(-0.7,0) 2(0.7,0)
  silkscreen extent -0.15,-0.58 0.15,0.58, body extent -0.87,-0.47 0.87,0.47, height 0.95
"NY PMS 440 0025 PH" [mm] "4-40 nylon screw and mounting hole"
  round 8 hole 3.2: 1(0,0)
  body extent -3.3,-3.3 3.3,3.3, height 2.69
Pb-Free_Overlay_Small [mil]
  silkscreen extent -46,-46 46,46
POWERMITE [mil] "On Semi recommended land pattern, 457-04.pdf Rev 04E dated 2008-11-26"
  rect 105x100 smd: 1(-46,0)
  rect 30x50 smd: 2(46,0)
  silkscreen extent -124,-63 61,63, body extent -94,-40 59,40, height 45
RGE0024B [mm] "QFN, 24-Leads, Body 4x4mm, Pitch 0.5mm, Thermal Pad 2.45x2.45mm, TI Recommended"
  oval 0.6x0.24 smd: 1(-1.9,1.25) 2(-1.9,0.75) 3(-1.9,0.25) 4(-1.9,-0.25) 5(-1.9,-0.75) 6(-1.9,-1.25) 13(1.9,-1.25) 14(1.9,-0.75) 15(1.9,-0.25) 16(1.9,0.25) 17(1.9,0.75) 18(1.9,1.25)
  oval 0.24x0.6 smd: 7(-1.25,-1.9) 8(-0.75,-1.9) 9(-0.25,-1.9) 10(0.25,-1.9) 11(0.75,-1.9) 12(1.25,-1.9) 19(1.25,1.9) 20(0.75,1.9) 21(0.25,1.9) 22(-0.25,1.9) 23(-0.75,1.9) 24(-1.25,1.9)
  rect 2.45x2.45 smd paste-1.225: 25(0,0)
  silkscreen extent -2.22,-2.22 2.22,2.22, body extent -2.07,-2.07 2.07,2.07, height 1.01
Samtec_SSW-116-01-x-D [mm] "Receptacle, 2.54mm, 16x2, TH"
  rect 1.55x1.55 hole 1.04: 1(-19.05,1.27)
  round 1.55 hole 1.04: 2(-19.05,-1.27) 3(-16.51,1.27) 4(-16.51,-1.27) 5(-13.97,1.27) 6(-13.97,-1.27) 7(-11.43,1.27) 8(-11.43,-1.27) 9(-8.89,1.27) 10(-8.89,-1.27) 11(-6.35,1.27) 12(-6.35,-1.27) 13(-3.81,1.27) 14(-3.81,-1.27) 15(-1.27,1.27) 16(-1.27,-1.27) 17(1.27,1.27) 18(1.27,-1.27) 19(3.81,1.27) 20(3.81,-1.27) 21(6.35,1.27) 22(6.35,-1.27) 23(8.89,1.27) 24(8.89,-1.27) 25(11.43,1.27) 26(11.43,-1.27) 27(13.97,1.27) 28(13.97,-1.27) 29(16.51,1.27) 30(16.51,-1.27) 31(19.05,1.27) 32(19.05,-1.27)
  silkscreen extent -20.57,-2.48 20.57,2.8, body extent -20.57,-2.48 20.57,2.48, height 8.51
SDC08A [mm] "SON, 8-Leads, Body 4x4mm, Pitch 0.8mm, NSC Recommended"
  rect 0.6x0.3 smd paste-0.15 mask+0.051: 1(-1.9,1.2) 2(-1.9,0.4) 3(-1.9,-0.4) 4(-1.9,-1.2) 5(1.9,-1.2) 6(1.9,-0.4) 7(1.9,0.4) 8(1.9,1.2)
  rect 2.6x3 smd paste-1.5 mask+0.051: 9(0,0)
  silkscreen extent -3.02,-2.2 2.35,2.2, body extent -2.05,-2.05 2.05,2.05, height 0.8
SOD-123 [mm] "On Semi recommended land pattern"
  rect 0.915x1.22 smd: 1(-1.637,0) 2(1.637,0)
  silkscreen extent -2.74,-1.17 2.03,1.17, body extent -1.93,-0.9 1.93,0.9, height 1.35
SOD-323#1 [mm] "NXP recommended land pattern"
  rect 0.6x0.6 smd: 1(-1.1,0) 2(1.1,0)
  silkscreen extent -2.06,-0.86 1.53,0.86, body extent -1.3,-0.67 1.3,0.68, height 1.1
SOD-323#2 [mm] "NXP recommended land pattern"
  rect 0.6x0.6 smd paste+0: 1(-1.1,0) 2(1.1,0)
  silkscreen extent -2.06,-0.86 1.53,0.86, body extent -1.3,-0.67 1.3,0.68, height 1.1
sod-323 [mm] "NXP recommended land pattern"
  rect 0.6x0.6 smd: 1(-1.1,0) 2(1.1,0)
  silkscreen extent -2.06,-0.86 1.53,0.86, body extent -1.3,-0.67 1.3,0.68, height 1.1
TE_5-146280-3 [mm] "Header, 2.54mm, 3x1, TH"
  rect 0.76x2.29 hole 0.89: 1(-2.54,0) 2(0,0) 3(2.54,0)
  silkscreen extent -3.9,-1.17 3.61,1.17, body extent -3.61,-1.17 3.61,1.17, height 8.13
TH-40 [mil]
  round 75 hole 40: 1(0,0)
TI_Stacked_Overlay_Small [mil]
  silkscreen extent -418,-98 418,98
TP1_PD40_D0.5_S50 [mil]
  round 40 hole 20: 1(0,0)
  silkscreen extent -25,-25 25,25
TP-040_RND [mil]
  round 70 / inner round 62 / far side round 62 hole 40: 1(0,0)
TP_H045P075 [mil] "TP_H0.45P0.75"
  round 35 hole 17.72: 1(0,0)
